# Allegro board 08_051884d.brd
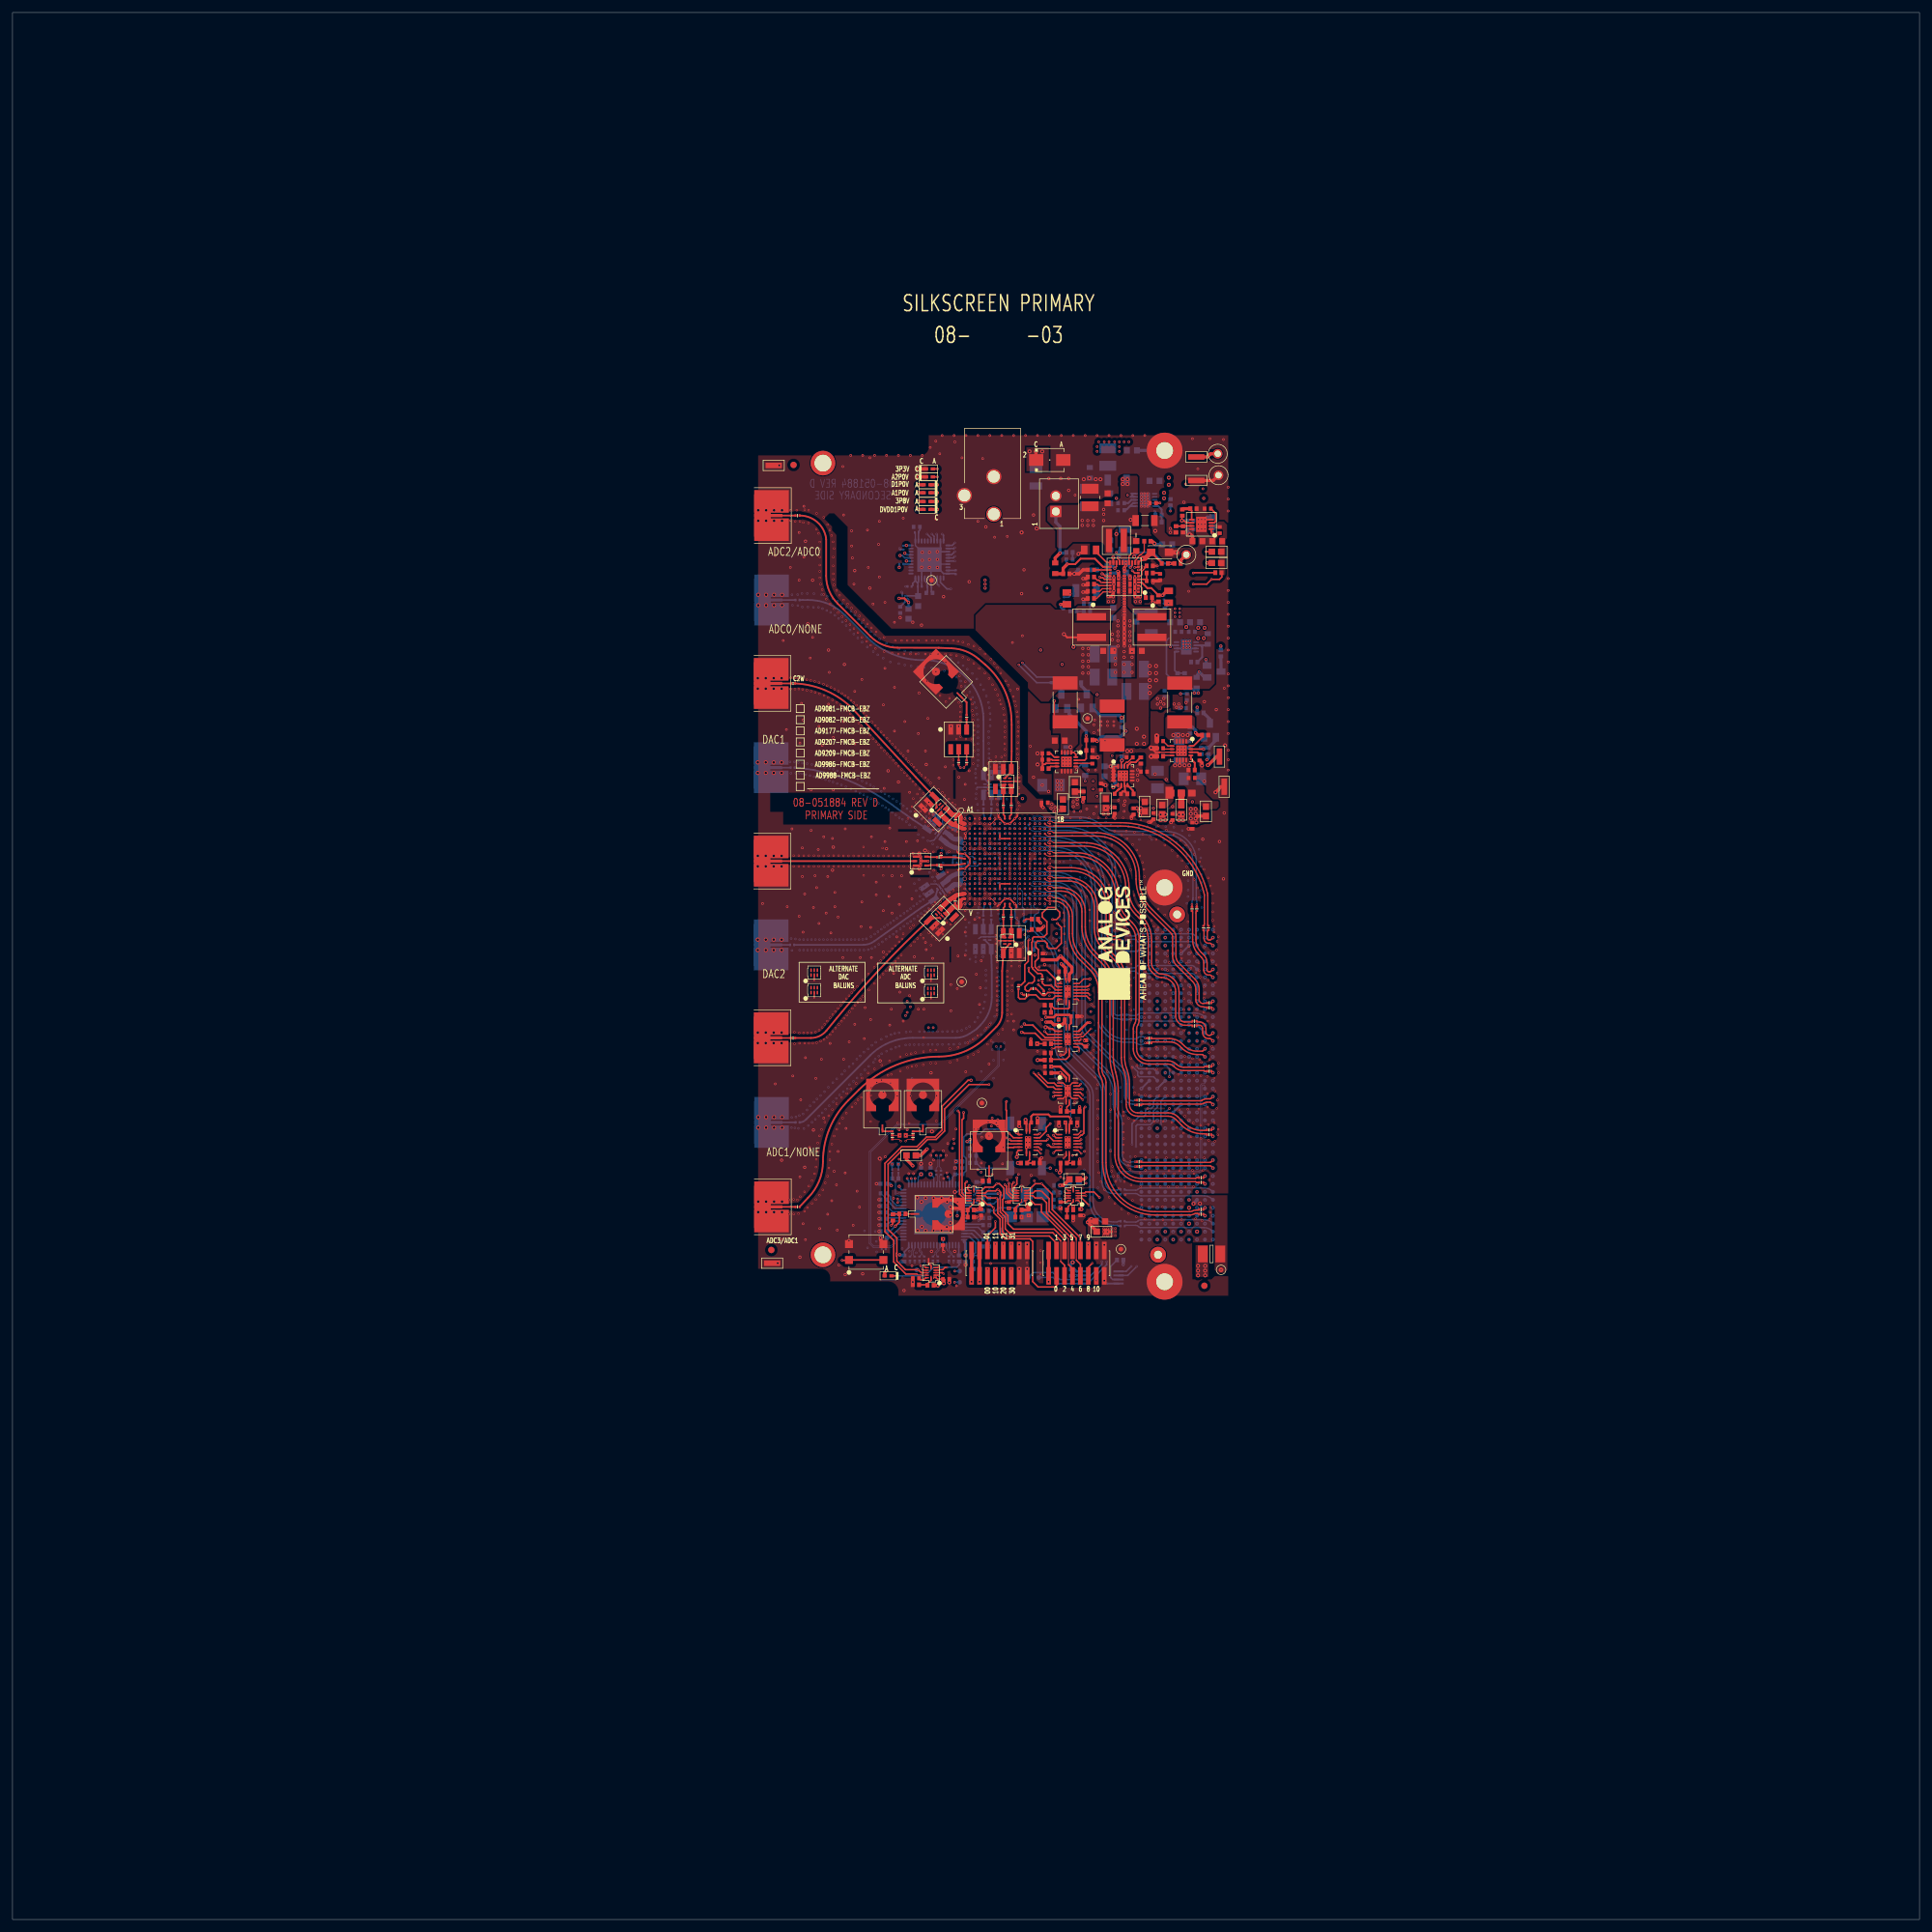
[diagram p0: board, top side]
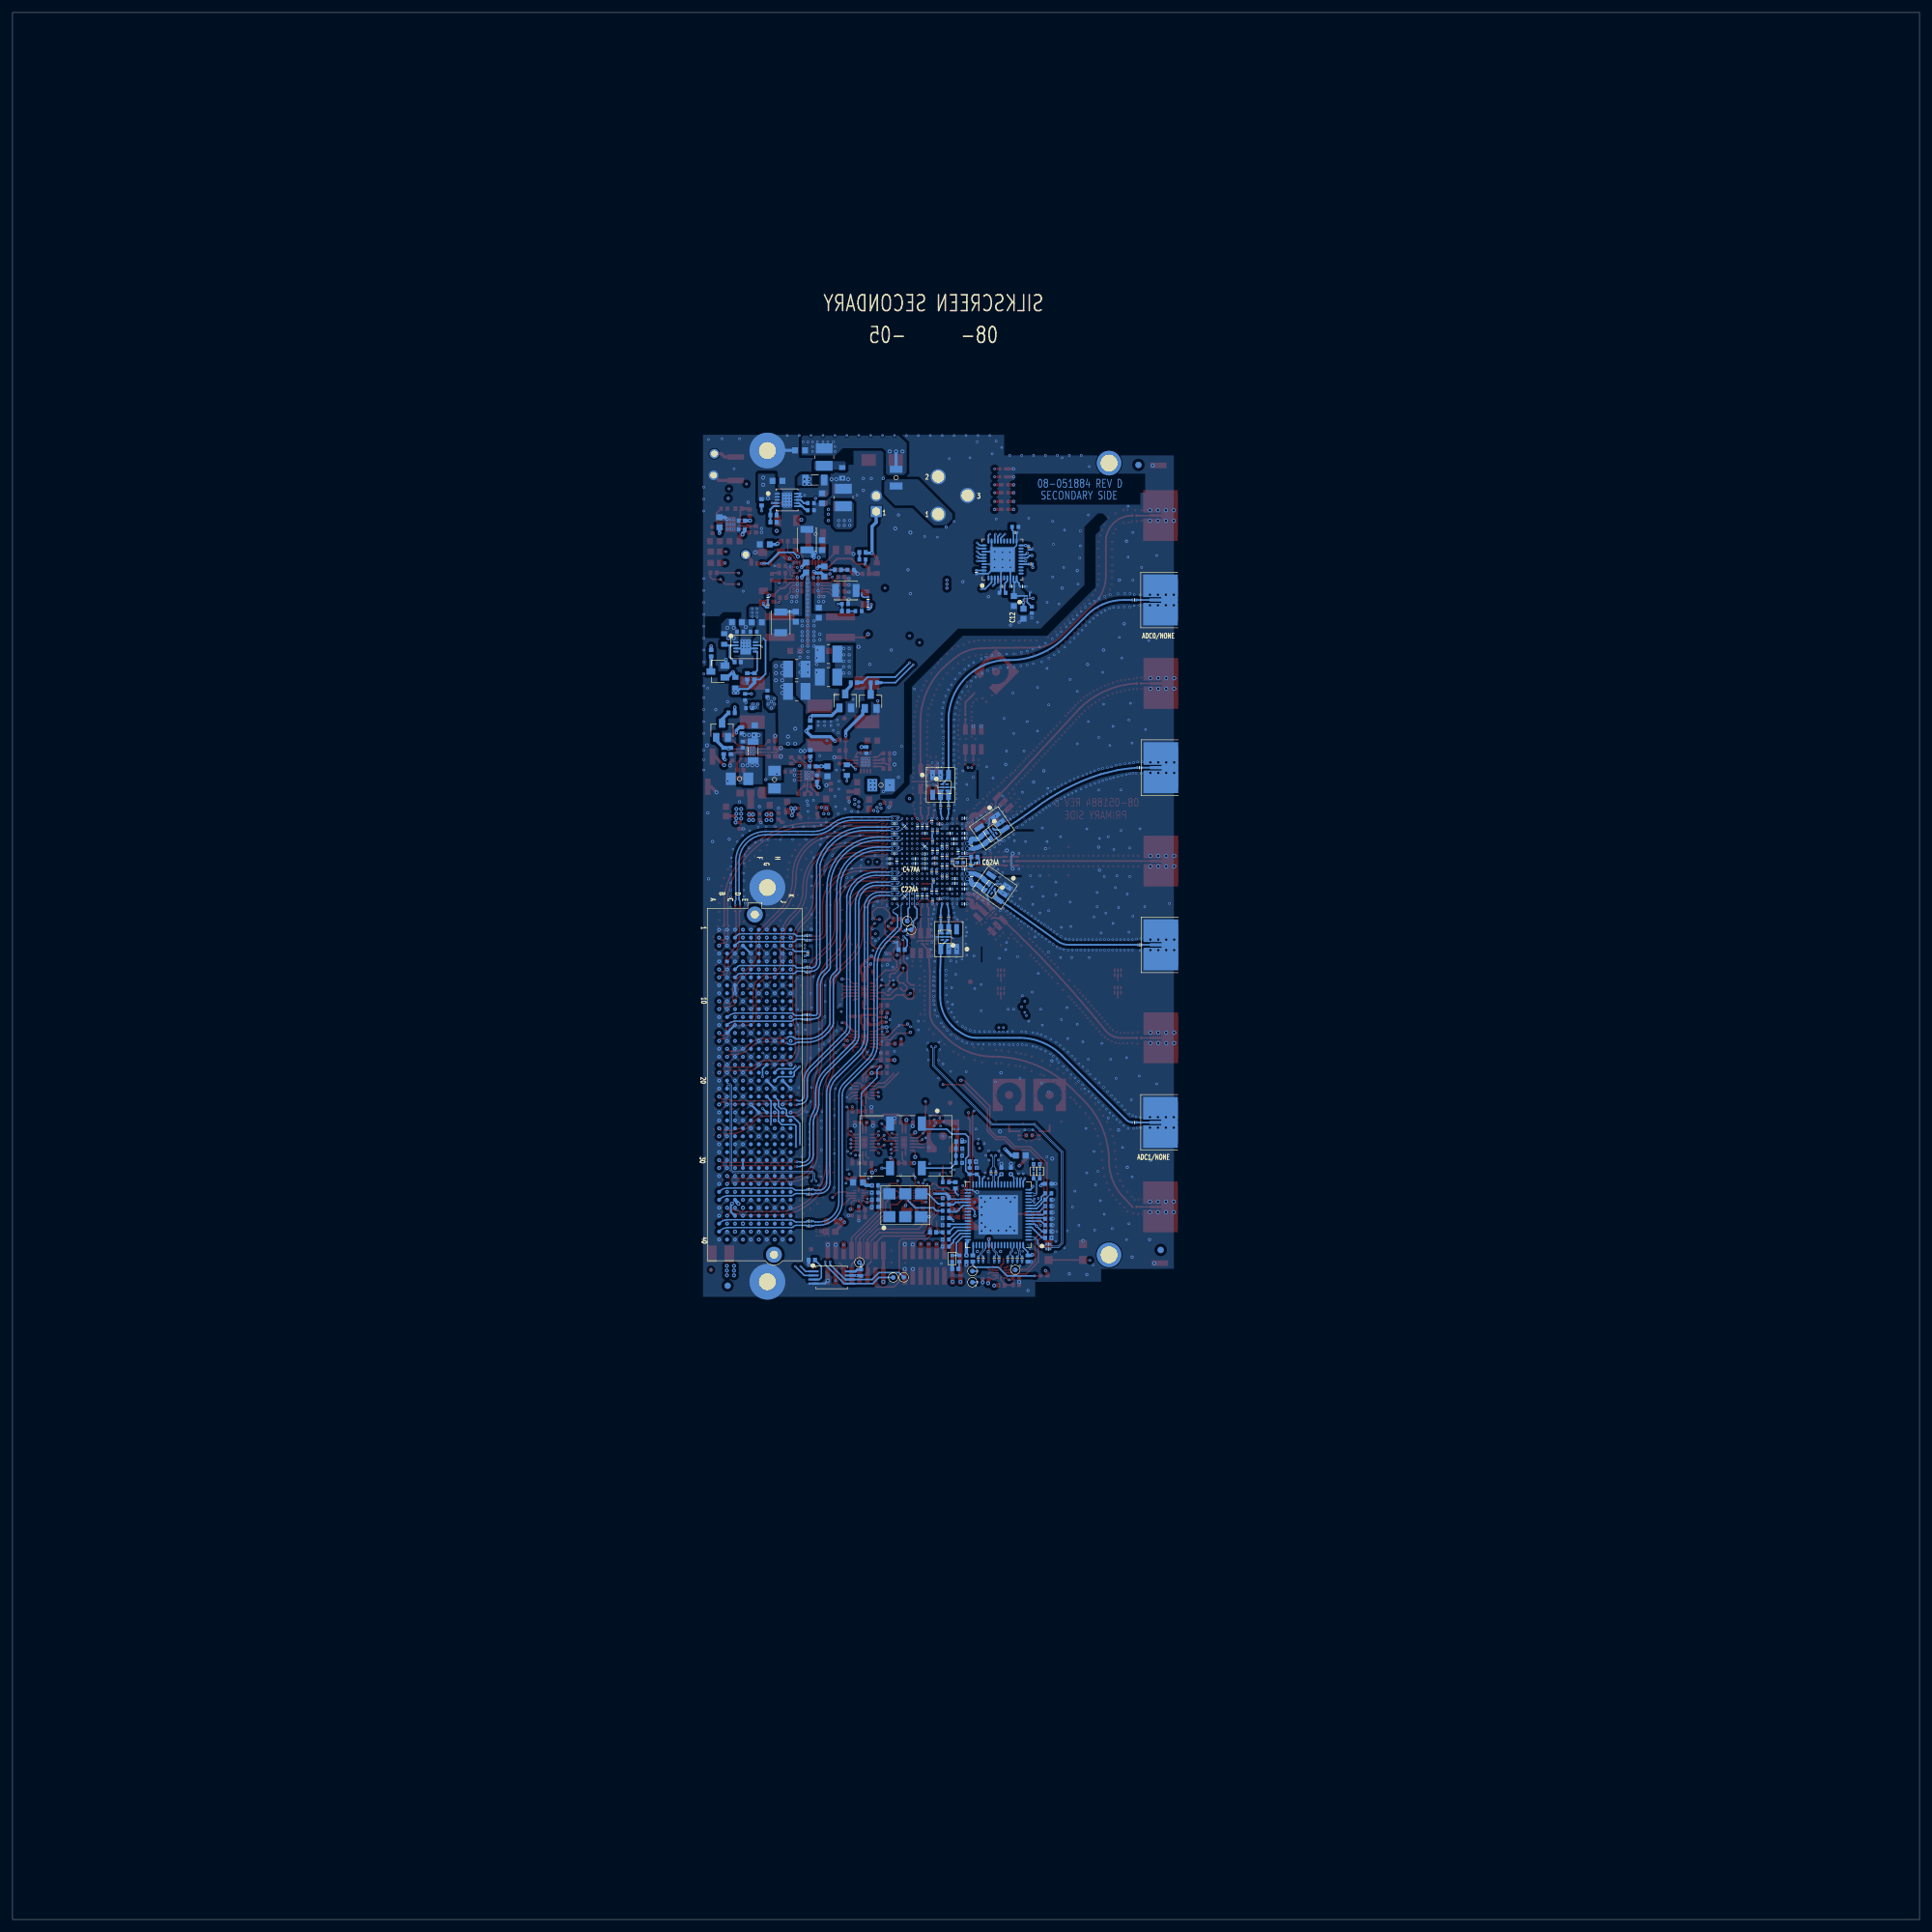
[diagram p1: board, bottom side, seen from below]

Outline 304.8 x 304.8 mm; copper layers: TOP, L2_GROUND, L3_SIGNAL, L4_GROUND, L5_POWER_ANALOG, L6_GROUND, L7_POWER_DIGITAL, L8_GROUND, L9_POWER_DVDD1, L10_SIGNAL, L11_GROUND, BOTTOM. Coordinates in mm from the lower left corner of the outline.
Outline path: 0,304.8 0,0 304.8,0 304.8,304.8 0,304.8

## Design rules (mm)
constraint set DEFAULT: min track width 0.241
net group CLK: nets HMC_CLK_N HMC_CLK_P
net group CLKOUT_0_N: nets CLKOUT_0_N UNNAMED_6_ADHMC7044_I49_CLKOUT0N
net group CLKOUT_0_P: nets CLKOUT_0_P UNNAMED_6_ADHMC7044_I49_CLKOUT0
net group CLKOUT_6_N: nets CLKOUT_6_N UNNAMED_6_ADHMC7044_I49_CLKOUT6N
net group CLKOUT_6_P: nets CLKOUT_6_P UNNAMED_6_ADHMC7044_I49_CLKOUT6_1
net group CLKOUT_8_N: nets CLKOUT_8_N UNNAMED_6_ADHMC7044_I49_CLKOUT8N
net group CLKOUT_8_P: nets CLKOUT_8_P UNNAMED_6_ADHMC7044_I49_CLKOUT8_1
net group CLKOUT_10_N: nets CLKOUT_10_N UNNAMED_6_ADHMC7044_I49_CLKOUT10N
net group CLKOUT_10_P: nets CLKOUT_10_P UNNAMED_6_ADHMC7044_I49_CLKOUT10
net group DAC0: nets DAC_N0 DAC_P0
net group DAC1: nets DAC_N1 DAC_P1
net group DAC2: nets DAC_N2 DAC_P2
net group DAC3: nets DAC_N3 DAC_P3
net group DP1: nets SYNCOUT_N0 SYNCOUT_P0
net group DP2: nets SYNCOUT_N1 SYNCOUT_P1
net group DP3: nets ADCDRV_N ADCDRV_P
net group DP4: nets UNNAMED_6_CAP_I146_N1 UNNAMED_6_CAP_I152_N1
net group FPGA_REFCLK_IN_N: nets FPGA_REFCLK_IN_N UNNAMED_6_ADHMC7044_I49_CLKOUT12N
net group FPGA_REFCLK_IN_P: nets FPGA_REFCLK_IN_P UNNAMED_6_ADHMC7044_I49_CLKOUT12
net group FPGA_SERDIN_N0: nets FPGA_SERDIN_N0 SERDOUT_N0
net group FPGA_SERDIN_N1: nets FPGA_SERDIN_N1 SERDOUT_N1
net group FPGA_SERDIN_N2: nets FPGA_SERDIN_N2 SERDOUT_N2
net group FPGA_SERDIN_N3: nets FPGA_SERDIN_N3 SERDOUT_N3
net group FPGA_SERDIN_N4: nets FPGA_SERDIN_N4 SERDOUT_N4
net group FPGA_SERDIN_N5: nets FPGA_SERDIN_N5 SERDOUT_N5
net group FPGA_SERDIN_N6: nets FPGA_SERDIN_N6 SERDOUT_N6
net group FPGA_SERDIN_N7: nets FPGA_SERDIN_N7 SERDOUT_N7
net group FPGA_SERDIN_P0: nets FPGA_SERDIN_P0 SERDOUT_P0
net group FPGA_SERDIN_P1: nets FPGA_SERDIN_P1 SERDOUT_P1
net group FPGA_SERDIN_P2: nets FPGA_SERDIN_P2 SERDOUT_P2
net group FPGA_SERDIN_P3: nets FPGA_SERDIN_P3 SERDOUT_P3
net group FPGA_SERDIN_P4: nets FPGA_SERDIN_P4 SERDOUT_P4
net group FPGA_SERDIN_P5: nets FPGA_SERDIN_P5 SERDOUT_P5
net group FPGA_SERDIN_P6: nets FPGA_SERDIN_P6 SERDOUT_P6
net group FPGA_SERDIN_P7: nets FPGA_SERDIN_P7 SERDOUT_P7
net group FPGA_SERDOUT_N0: nets FPGA_SERDOUT_N0 SERDIN_N0
net group FPGA_SERDOUT_N1: nets FPGA_SERDOUT_N1 SERDIN_N1
net group FPGA_SERDOUT_N2: nets FPGA_SERDOUT_N2 SERDIN_N2
net group FPGA_SERDOUT_N3: nets FPGA_SERDOUT_N3 SERDIN_N3
net group FPGA_SERDOUT_N4: nets FPGA_SERDOUT_N4 SERDIN_N4
net group FPGA_SERDOUT_N5: nets FPGA_SERDOUT_N5 SERDIN_N5
net group FPGA_SERDOUT_N6: nets FPGA_SERDOUT_N6 SERDIN_N6
net group FPGA_SERDOUT_N7: nets FPGA_SERDOUT_N7 SERDIN_N7
net group FPGA_SERDOUT_P0: nets FPGA_SERDOUT_P0 SERDIN_P0
net group FPGA_SERDOUT_P1: nets FPGA_SERDOUT_P1 SERDIN_P1
net group FPGA_SERDOUT_P2: nets FPGA_SERDOUT_P2 SERDIN_P2
net group FPGA_SERDOUT_P3: nets FPGA_SERDOUT_P3 SERDIN_P3
net group FPGA_SERDOUT_P4: nets FPGA_SERDOUT_P4 SERDIN_P4
net group FPGA_SERDOUT_P5: nets FPGA_SERDOUT_P5 SERDIN_P5
net group FPGA_SERDOUT_P6: nets FPGA_SERDOUT_P6 SERDIN_P6
net group FPGA_SERDOUT_P7: nets FPGA_SERDOUT_P7 SERDIN_P7
net group SYNCIN0: nets SYNCIN_N0 SYNCIN_P0
net group SYNCIN1: nets SYNCIN_N1 SYNCIN_P1
net group SYSREF: nets HMC_SYSREF_N HMC_SYSREF_P
net group SYSREF2_N: nets SYSREF2_N UNNAMED_6_ADHMC7044_I49_SCLKOUT13N
net group SYSREF2_P: nets SYSREF2_P UNNAMED_6_ADHMC7044_I49_SCLKOUT13
net group SYSREF3: nets SYSREF_N SYSREF_P

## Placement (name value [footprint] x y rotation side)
3P3V  RCU-0C  [CNTERCU]  192.91 185.88 90 top
12P0V  RCU-0C  [CNTERCU]  189.2 233.76 0 top
ADC0  142-0761-841  [CNSMAL554W247H118]  118.55 210.9 180 bottom
ADC1  142-0761-841  [CNSMAL554W247H118]  118.55 127.4 180 bottom
ADC2  142-0761-841  [CNSMAL554W247H118]  118.55 224.4 180 top
ADC3  142-0761-841  [CNSMAL554W247H118]  118.55 113.9 180 top
ADC_CLK  85305-0232  [CNSMASQ197H161]  149.22 197.82 45 top
AGC  FTSH-108-01-F-DV-K  [CNHDR2X8H251]  157.73 104.9 0 top
C1  1uF  [C0402]  146.56 212.04 0 bottom
C1A  10uF  [C1210-2]  175.06 233.75 270 bottom
C1AA  0.1uF  [C0201]  152.65 176.02 180 bottom
C1B  4.7uF  [C0402]  139.25 110.98 180 bottom
C1C  0.1uF  [C0201]  143.93 125.02 90 top
C1D  1.5pF  [C0402]  141.09 118.44 180 bottom
C1FF  0.1uF  [C0402]  164.68 153.89 270 top
C1G  0.1uF  [C0201]  177.75 157.28 180 bottom
C1H  0.1uF  [C0201]  177.75 156.51 180 bottom
C1I  0.1uF  [C0201]  189.28 161.52 90 top
C1J  0.1uF  [C0201]  188.52 161.52 90 top
C1K  0.1uF  [C0402]  169.16 103.38 270 bottom
C1LL  0.1uF  [C0603]  175.93 208.86 270 bottom
C1R  0.1uF  [C0201]  151.23 184.94 90 top
C1S  0.1uF  [C0201]  155.19 177.9 90 bottom
C1T  0.1uF  [C0201]  156.44 160.14 270 bottom
C1U  0.1uF  [C0201]  159.64 178.05 90 top
C1V  0.1uF  [C0201]  158.37 160.25 270 top
C1X  10uF  [C0603]  174.55 183.52 270 bottom
C2  1uF  [C0402]  144.52 222.58 180 bottom
C2A  0.1uF  [C0603]  178.92 234.81 0 bottom
C2AA  0.1uF  [C0201]  154.94 173.61 0 bottom
C2B  4.7uF  [C0402]  139.25 112 180 bottom
C2C  0.1uF  [C0201]  143.93 125.65 90 top
C2D  1.5pF  [C0402]  141.09 120.73 180 bottom
C2FF  0.1uF  [C0402]  169.67 144.35 180 top
C2G  0.1uF  [C0201]  191.26 126.21 180 top
C2H  0.1uF  [C0201]  191.26 125.45 180 top
C2I  0.1uF  [C0201]  177.75 152.2 180 bottom
C2J  0.1uF  [C0201]  177.75 151.43 180 bottom
C2LL  10pF  [C0402]  171.74 210.26 180 bottom
C2M  10uF  [C0603]  186.18 190.07 90 bottom
C2NN  10uF  [C0603]  167.38 188.42 180 top
C2P  10uF  [C0603]  189.39 220.29 0 top
C2Q  10uF  [C0603]  185.83 207.34 0 bottom
C2R  0.1uF  [C0201]  152.5 184.94 90 top
C2S  0.1uF  [C0201]  156.46 177.9 90 bottom
C2T  0.1uF  [C0201]  155.17 160.14 270 bottom
C2U  0.1uF  [C0201]  158.37 178.05 90 top
C2V  0.1uF  [C0201]  159.64 160.25 270 top
C2W  0.1uF  [C0201]  124.76 197.56 180 top
C2X  0.1uF  [C0201]  124.69 184.1 180 bottom
C2XA  1uF  [C0402]  176.91 184.3 0 bottom
C2Y  0.1uF  [C0201]  124.61 155.78 180 bottom
C2Z  0.1uF  [C0201]  124.76 140.9 180 top
C3  0.1uF  [C0201]  155.45 168.35 270 bottom
C3B  1uF  [C0402]  166.94 113.9 0 bottom
C3C  0.1uF  [C0201]  140.63 125.02 90 top
C3D  0.1uF  [C0201]  148.4 170.11 270 top
C3FF  0.1uF  [C0402]  165.5 136.32 0 top
C3G  0.1uF  [C0201]  189.99 118.57 180 top
C3H  0.1uF  [C0201]  189.99 117.81 180 top
C3I  0.1uF  [C0201]  177.77 144.6 180 bottom
C3J  0.1uF  [C0201]  177.77 143.84 180 bottom
C3LL  0.1uF  [C0603]  179.61 208.23 270 bottom
C3M  1uF  [C0402]  188.08 187.78 270 bottom
C3NN  1uF  [C0402]  168.3 186.89 270 bottom
C3P  1uF  [C0402]  188.25 222.2 0 bottom
C3R  0.1uF  [C0201]  152.5 192.18 90 top
C3S  0.1uF  [C0201]  125.48 210.9 180 bottom
C3T  0.1uF  [C0201]  125.47 127.41 180 bottom
C3U  0.1uF  [C0201]  125.48 224.4 180 top
C3V  0.1uF  [C0201]  125.48 113.9 180 top
C4  0.1uF  [C0201]  150.75 215.34 270 bottom
C4AA  0.1uF  [C0201]  152.65 172.85 180 bottom
C4B  1uF  [C0402]  153.52 122.07 180 bottom
C4C  0.1uF  [C0201]  140.63 125.65 90 top
C4D  0.1uF  [C0201]  148.08 169.8 180 top
C4FF  0.1uF  [C0402]  167.77 151.51 180 top
C4G  0.1uF  [C0201]  189.99 113.49 180 top
C4H  0.1uF  [C0201]  189.99 112.73 180 top
C4I  0.1uF  [C0201]  181.71 140.87 180 top
C4J  0.1uF  [C0201]  181.71 140.11 180 top
C4LL  100uF  [C1210-2]  174.37 202.26 0 bottom
C4M  1uF  [C0402]  183.41 187.2 180 top
C4NN  1uF  [C0402]  165.1 185.37 180 top
C4P  1uF  [C0402]  191.04 225.5 180 top
C4Q  1uF  [C0402]  186.34 205.82 0 bottom
C4X  1uF  [C0402]  176.65 179.91 0 top
C5  0.1uF  [C0201]  146.56 213.06 0 bottom
C5AA  0.1uF  [C0201]  154.31 172.72 0 bottom
C5B  4.7uF  [C0402]  139.25 113.02 180 bottom
C5D  0.1uF  [C0201]  148.39 168.21 90 top
C5FF  0.1uF  [C0402]  167.69 143.84 180 top
C5G  0.1uF  [C0201]  180.06 130.96 180 top
C5H  0.1uF  [C0201]  180.06 130.2 180 top
C5I  0.1uF  [C0201]  191.29 136.35 180 top
C5J  0.1uF  [C0201]  191.29 135.59 180 top
C5LL  0.1uF  [C0603]  175.13 202.77 0 top
C5M  1uF  [C0402]  183.41 188.34 180 top
C5NN  1uF  [C0402]  165.1 186.39 180 top
C5OO  1uF  [C0402]  177.2 226.39 180 bottom
C5P  10uF  [C0603]  191.8 223.34 90 bottom
C5Q  10uF  [C0603]  189.01 207.34 180 bottom
C5X  1uF  [C0402]  176.22 182.37 90 bottom
C6  0.1uF  [C0201]  144.52 221.69 180 bottom
C6AA  0.1uF  [C0201]  155.45 169.88 90 bottom
C6B  0.1uF  [C0402]  166.94 115.05 0 bottom
C6D  0.1uF  [C0201]  148.08 168.53 180 top
C6FF  0.1uF  [C0402]  165.53 135.31 180 top
C6G  0.1uF  [C0201]  177.44 111.61 180 bottom
C6H  0.1uF  [C0201]  177.44 110.85 180 bottom
C6I  0.1uF  [C0201]  188.92 143.59 180 top
C6J  0.1uF  [C0201]  188.92 142.82 180 top
C6LL  10pF  [C0402]  172.37 215.72 180 top
C6M  0.01uF  [C0402]  189.74 185.75 270 top
C6NN  10uF  [C0402]  171.19 179.78 270 top
C6OO  10uF  [C0603]  143.63 122.12 180 bottom
C6P  10uF  [C0402]  187.7 195.4 270 bottom
C6Q  1uF  [C0402]  188.5 205.82 180 bottom
C6X  0.01uF  [C0402]  178.56 185.75 180 top
C7  0.1uF  [C0201]  145.03 213.06 0 bottom
C7AA  0.1uF  [C0201]  152.65 170.43 180 bottom
C7B  0.1uF  [C0402]  153.52 123.22 180 bottom
C7G  0.1uF  [C0201]  177.44 116.69 180 bottom
C7H  0.1uF  [C0201]  177.44 115.93 180 bottom
C7I  0.1uF  [C0201]  191.29 146.51 180 top
C7J  0.1uF  [C0201]  191.29 145.75 180 top
C7LL  4.7uF  [C1206H71-2]  183.42 218.52 0 top
C7M  47uF  [C1206H71]  188.59 182.32 0 bottom
C7NN  10uF  [C0402]  176.15 177.24 270 top
C7OO  10uF  [C0603]  175.42 227.15 270 bottom
C7P  1uF  [C0402]  188.25 223.6 0 bottom
C7X  47uF  [C1206H71]  183 182.2 90 bottom
C8  0.1uF  [C0201]  143.38 213.06 180 bottom
C8AA  0.1uF  [C0201]  154.31 171.96 0 bottom
C8B  1uF  [C0402]  139.25 115.05 180 bottom
C8FF  0.1uF  [C0402]  163.32 127.38 180 top
C8G  0.1uF  [C0201]  180.06 121.11 180 top
C8H  0.1uF  [C0201]  180.06 120.35 180 top
C8I  0.1uF  [C0201]  191.13 158.5 90 top
C8J  0.1uF  [C0201]  190.37 158.5 90 top
C8LL  4.7uF  [C0603]  184.56 219.79 0 bottom
C8M  1uF  [C0402]  188.47 182.45 0 top
C8NN  0.01uF  [C0402]  172.59 185.24 90 top
C8OO  10uF  [C0603]  169.67 117.81 0 bottom
C8P  10uF  [C0603]  192.54 220.29 180 top
C8X  1uF  [C0402]  180.85 183.47 0 top
C9  0.1uF  [C0201]  142.36 219.28 270 bottom
C9AA  0.1uF  [C0201]  156.21 169.93 90 bottom
C9B  100pF  [C0402]  166.94 116.19 0 bottom
C9FF  0.1uF  [C0402]  169.67 127.38 180 top
C9LL  1000pF  [C0402]  183.42 214.58 270 top
C9M  10uF  [C0402]  188.59 174.83 270 top
C9NN  47uF  [C1206H71]  165.99 181.31 180 bottom
C9OO  1uF  [C0402]  177.2 225.25 180 bottom
C9P  1uF  [C0402]  192.94 222.07 270 top
C9X  10uF  [C0402]  179.19 177.12 270 top
C10  0.01uF  [C0201]  168.05 209.75 270 bottom
C10AA  0.1uF  [C0201]  152.63 167.87 180 bottom
C10B  100pF  [C0402]  153.52 120.93 180 bottom
C10FF  0.1uF  [C0402]  161.42 127.38 180 top
C10LL  10pF  [C0402]  181.77 213.94 0 top
C10NN  1uF  [C0402]  173.99 181.05 90 top
C10X  10uF  [C0402]  185.42 176.23 270 top
C11  0.01uF  [C0201]  184.05 210.01 270 bottom
C11AA  0.1uF  [C0201]  154.18 166.37 0 bottom
C11B  0.1uF  [C0402]  155.63 114.29 180 bottom
C11FF  0.1uF  [C0402]  167.77 127.38 180 top
C11LL  0.1uF  [C0603]  177.96 216.1 270 bottom
C12  2.2uF  [C0603]  144.75 210.73 270 bottom
C12AA  0.1uF  [C0201]  156.21 168.4 270 bottom
C12B  0.1uF  [C0402]  155.63 113.27 180 bottom
C12FF  0.1uF  [C0402]  151.64 114.17 90 top
C12LL  0.1uF  [C0603]  175.04 215.47 90 bottom
C12N  10uF  [C0402]  164.97 178.51 180 top
C13  2.2uF  [C0603]  143.22 208.7 270 bottom
C13AA  0.1uF  [C0201]  152.65 165.48 180 bottom
C13B  0.1uF  [C0402]  155.63 117.84 180 bottom
C13FF  0.1uF  [C0402]  159.26 114.17 90 top
C13LL  0.01uF  [C0402]  168.94 217.37 0 bottom
C14  1000pF  [C0402]  141.88 209.31 270 bottom
C14AA  0.1uF  [C0201]  154.18 165.61 0 bottom
C14FF  0.1uF  [C0402]  167.51 114.17 90 top
C14LL  0.1uF  [C0603]  179.61 219.53 90 top
C14OO  1uF  [C0402]  182.28 226.39 180 top
C15  10uF  [C0402]  184.15 195.91 90 bottom
C15AA  0.1uF  [C0201]  155.45 171.58 270 bottom
C15B  0.1uF  [C0402]  155.63 109.84 180 bottom
C15FF  0.1uF  [C0402]  154.81 113.03 270 top
C16  10uF  [C0402]  187.07 193.63 0 bottom
C16AA  0.1uF  [C0201]  152.65 162.31 180 bottom
C16B  0.1uF  [C0402]  155.63 108.7 180 bottom
C16FF  0.1uF  [C0402]  162.43 113.03 270 top
C17  0.1uF  [C0201]  157.73 162.76 270 bottom
C17AA  0.1uF  [C0201]  154.94 164.72 0 bottom
C17B  0.1uF  [C0402]  139.25 116.06 180 bottom
C17FF  0.1uF  [C0402]  170.69 113.03 270 top
C17OO  10uF  [C0603]  173.86 111.58 0 top
C18  0.1uF  [C0201]  157.86 175.59 90 bottom
C18AA  0.1uF  [C0201]  155.45 166.75 90 bottom
C18B  4.7uF  [C0402]  155.63 110.98 0 bottom
C18FF  0.1uF  [C0402]  144.4 102.49 0 top
C19  0.1uF  [C0201]  156.59 163.15 180 bottom
C19AA  0.1uF  [C0201]  158.62 174.75 90 bottom
C19B  4.7uF  [C0402]  155.63 107.55 0 bottom
C19FF  0.1uF  [C0402]  149.22 102.36 0 top
C20  0.1uF  [C0201]  156.59 175.08 180 bottom
C20AA  0.1uF  [C0201]  159 173.61 180 bottom
C20B  0.1uF  [C0402]  139.25 114.03 0 bottom
C21AA  0.1uF  [C0201]  158.62 163.58 270 bottom
C21B  0.1uF  [C0402]  139.25 117.59 0 bottom
C22AA  0.1uF  [C0201]  159 164.72 180 bottom
C22B  0.1uF  [C0402]  145.22 119.62 270 bottom
C22LL  100uF  [C1210-2]  171.99 227.28 90 bottom
C23AA  0.1uF  [C0201]  157.73 173.99 90 bottom
C23B  0.1uF  [C0402]  146.74 119.62 270 bottom
C23LL  100uF  [C1210-2]  179.45 199.85 180 bottom
C23X  10uF  [C0402]  182.37 176.35 270 top
C24AA  0.1uF  [C0201]  159.38 174.75 90 bottom
C24B  0.1uF  [C0402]  155.63 115.3 180 bottom
C24LL  100uF  [C1210-2]  172.24 227.28 90 top
C25AA  0.1uF  [C0201]  157.73 172.34 270 bottom
C25B  0.1uF  [C0402]  155.63 112.13 180 bottom
C25LL  0.1uF  [C0603]  175.42 219.66 90 bottom
C26B  0.1uF  [C0402]  142.55 105.65 270 bottom
C27AA  0.1uF  [C0201]  159.38 163.58 270 bottom
C27B  0.1uF  [C0402]  148.71 108.28 270 top
C27LL  100uF  [C1210-2]  179.45 196.29 180 bottom
C28B  0.1uF  [C0402]  152.33 105.65 270 bottom
C28LL  0.1uF  [C0603]  175.04 227.15 90 top
C29AA  0.1uF  [C0201]  156.97 173.99 90 bottom
C29B  0.1uF  [C0201]  139.25 107.17 180 bottom
C29LL  0.1uF  [C0603]  179.7 202.77 180 top
C30AA  0.1uF  [C0201]  156.97 170.81 270 bottom
C30B  0.1uF  [C0201]  139.25 107.94 180 bottom
C30LL  22uF  [C1210H106]  182.02 207.34 270 bottom
C31AA  0.1uF  [C0201]  157.1 164.34 270 bottom
C31B  0.1uF  [C0201]  147.63 119.37 90 bottom
C31LL  22uF  [C1210H106]  171.61 212.42 180 bottom
C32AA  0.1uF  [C0201]  157.73 170.81 270 bottom
C32B  0.1uF  [C0201]  148.39 119.37 90 bottom
C33AA  0.1uF  [C0201]  157.61 165.99 90 bottom
C33B  0.1uF  [C0201]  150.43 105.65 270 bottom
C34AA  0.1uF  [C0201]  160.15 174.75 270 bottom
C34B  0.1uF  [C0201]  149.66 105.65 270 bottom
C35AA  0.1uF  [C0201]  157.1 167.51 90 bottom
C35B  0.1uF  [C0201]  147.89 105.65 270 bottom
C36AA  0.1uF  [C0201]  157.86 164.34 270 bottom
C36B  0.1uF  [C0201]  147.12 105.65 270 bottom
C37AA  0.1uF  [C0201]  160.15 163.58 90 bottom
C37B  0.1uF  [C0201]  144.2 105.65 270 bottom
C38AA  0.1uF  [C0201]  157.86 167.51 90 bottom
C38B  0.1uF  [C0201]  143.44 105.65 270 bottom
C39AA  0.1uF  [C0201]  156.21 171.58 90 bottom
C39B  0.1uF  [C0201]  145.73 105.65 270 bottom
C40AA  0.1uF  [C0201]  156.21 166.75 270 bottom
C40B  0.1uF  [C0201]  144.96 105.65 270 bottom
C40LL  2200pF  [C0402]  170.85 215.72 180 bottom
C41AA  0.1uF  [C0201]  159 170.31 0 bottom
C41B  160pF  [C0402H22]  154.62 105.65 270 bottom
C41LL  22uF  [C1210H106]  177.83 220.55 90 bottom
C42AA  0.1uF  [C0201]  157.35 169.67 0 bottom
C42B  4700pF  [C0402]  153.47 105.65 270 bottom
C42LL  100uF  [C1210-2]  174.37 198.58 0 bottom
C43AA  0.1uF  [C0201]  159 169.55 0 bottom
C43B  4700pF  [C0402]  150.68 119.62 90 bottom
C43LL  1000pF  [C0402]  169.58 209.12 180 bottom
C44AA  0.1uF  [C0201]  157.35 168.78 0 bottom
C44B  1uF  [C0402]  151.82 119.62 90 bottom
C45AA  0.1uF  [C0201]  160.53 169.55 0 bottom
C46AA  0.1uF  [C0201]  159 168.78 0 bottom
C47AA  0.1uF  [C0201]  160.53 168.78 0 bottom
C48AA  0.1uF  [C0201]  152.65 173.61 180 bottom
C49AA  0.1uF  [C0201]  159 168.02 0 bottom
C50AA  0.1uF  [C0201]  152.65 164.72 180 bottom
C51AA  0.1uF  [C0201]  163.45 169.16 90 bottom
C52AA  0.1uF  [C0201]  163.83 175.16 180 bottom
C53AA  0.1uF  [C0201]  164.59 169.55 0 bottom
C54AA  0.1uF  [C0201]  163.83 173.56 180 bottom
C55AA  0.1uF  [C0201]  164.59 168.78 0 bottom
C56AA  0.1uF  [C0201]  163.83 171.96 180 bottom
C57AA  0.1uF  [C0201]  163.83 166.36 180 bottom
C58AA  0.1uF  [C0201]  163.83 170.36 180 bottom
C59AA  0.1uF  [C0201]  163.83 164.76 180 bottom
C60AA  0.1uF  [C0201]  163.83 163.14 180 bottom
C62AA  0.022uF  [C0201]  150.62 168.86 0 bottom
C63AA  0.033uF  [C0201]  154.63 169.09 90 bottom
C65AA  2200pF  [C0201]  151.64 168.61 270 bottom
C69AA  2.2uF  [C0402H22]  153.29 168.94 180 bottom
C70AA  0.1uF  [C0201]  159 171.53 225 bottom
C71AA  0.1uF  [C0201]  162.18 163.53 315 bottom
C72AA  0.1uF  [C0201]  162.18 174.7 45 bottom
C100  10uF  [C0603]  182.53 229.95 180 bottom
D1A  SMAJ12A  [DIOSMJ5_0]  165.78 233.28 0 top
DAC0  142-0761-841  [CNSMAL554W247H118]  118.49 197.56 180 top
DAC1  142-0761-841  [CNSMAL554W247H118]  118.49 184.1 180 bottom
DAC2  142-0761-841  [CNSMAL554W247H118]  118.49 155.78 180 bottom
DAC3  142-0761-841  [CNSMAL554W247H118]  118.49 140.92 180 top
DS1M  APHHS1005LSYCK/J3-PF  [LED0402_A]  146.17 225.38 180 top
DS1NN  APHHS1005LSYCK/J3-PF  [LED0402_A]  146.17 228.04 180 top
DS1P  APHHS1005LSYCK/J3-PF  [LED0402_A]  146.56 230.58 0 top
DS1Q  APHHS1005LSYCK/J3-PF  [LED0402_A]  146.17 226.65 180 top
DS1X  APHHS1005LSYCK/J3-PF  [LED0402_A]  146.17 229.31 180 top
DS100  APHHS1005LSYCK/J3-PF  [LED0402_A]  146.56 231.85 0 top
E1  22OHM AT 100 MEGHZ  [L0603H28]  192.45 216.82 180 top
E1B  120OHM  [L0402]  166.94 117.33 180 bottom
E1M  22OHM AT 100 MEGHZ  [L0603H28]  190.75 177.12 270 top
E1NN  22OHM AT 100 MEGHZ  [L0603H28]  169.8 181.03 270 top
E1OO  22OHM AT 100 MEGHZ  [L0603H28]  143.63 122.12 0 top
E1XX  22OHM AT 100 MEGHZ  [L0603H28]  180.97 177.88 270 top
E2  22OHM AT 100 MEGHZ  [L0603H28]  192.45 218.62 180 top
E2B  120OHM  [L0402]  153.52 124.36 0 bottom
E2NN  22OHM AT 100 MEGHZ  [L0603H28]  174.75 178.39 270 top
E2OO  22OHM AT 100 MEGHZ  [L0603H28]  174.04 109.93 180 top
E2XX  22OHM AT 100 MEGHZ  [L0603H28]  186.81 177.37 270 top
E3OO  22OHM AT 100 MEGHZ  [L0603H28]  169.67 118.31 180 top
E4NN  22OHM AT 100 MEGHZ  [L0603H28]  167.89 178.26 270 top
E4X  22OHM AT 100 MEGHZ  [L0603H28]  183.77 177.37 270 top
EXT_CLK  142-0761-841  [CNSMAL554W247H118]  118.49 169.17 180 top
EXT_HMCREF  85305-0232  [CNSMASQ197H161]  156.08 122.94 0 top
EXT_SYNC  85305-0232  [CNSMASQ197H161]  147.32 112.78 270 top
EXT_SYS_N  85305-0232  [CNSMASQ197H161]  139.04 129.49 0 top
EXT_SYS_P  85305-0232  [CNSMASQ197H161]  145.52 129.49 0 top
F1A  3A  [F1206]  163.57 230.46 90 bottom
GND0  RCU-0C  [CNTERCU]  189.2 230 0 top
GND1  RCU-0C  [CNTERCU]  193.67 181.05 270 top
GND2  RCU-0C  [CNTERCU]  121.67 232.41 0 top
GND3  RCU-0C  [CNTERCU]  121.41 104.9 0 top
GPIO  FTSH-108-01-F-DV-K  [CNHDR2X8H251]  170.05 104.9 0 top
HMC_STATUS  APHHS1005SURCK  [LED0402_A]  139.95 102.87 180 top
JP1  3PINJUMPER0603  [JUMPER0603_3P]  186.81 180.04 180 top
L1D  3.6nH  [L0201]  141.6 119.58 90 bottom
L1LL  800nH  [LSML208W216H122_A]  182.12 206.58 270 top
L2D  3.6nH  [L0201]  140.59 119.58 90 bottom
L2LL  800nH  [LSML208W216H122_A]  172.46 206.58 270 top
L3LL  4.7uH  [LSMSQ157H122]  176.43 220.42 180 top
NOREF  -  []  118.55 103.35 90 top
NOREF#2  -  []  118.55 103.35 90 top
NOREF#3  -  [unnamed#2]  129.54 106.24 0 top
NOREF#4  -  [unnamed#2]  129.54 232.78 0 top
NOREF#5  -  []  118.55 103.35 0 top
NOREF#6  -  []  84.33 219.91 270 top
NOREF#7  -  [unnamed#2]  124.84 232.49 0 top
NOREF#8  -  []  258.57 278.46 0 top
NOREF#9  -  []  406.65 57.74 0 top
NOREF#10  -  []  118.55 234.65 0 top
NOREF#11  -  []  118.55 103.35 0 top
NOREF#12  -  []  177.37 156.57 90 top
NOREF#13  -  []  145.65 237.95 0 top
NOREF#14  -  []  -222.25 -146.05 0 top
NOREF#15  -  []  -222.25 -146.05 0 top
NOREF#16  -  [unnamed#2]  121.28 107.01 0 top
NOREF#17  -  []  140.85 98.95 90 top
NOREF#18  -  []  -222.25 -146.05 0 top
NOREF#19  -  [unnamed#2]  190.5 101.3 0 top
NOREF#20  -  []  157.61 252.1 0 top
NOREF#21  -  []  -70.61 283.16 0 top
NOREF#22  -  []  130.05 101.25 90 top
NOREF#23  -  []  177.8 304.8 0 top
NOREF#24  -  []  195.04 98.95 90 top
NOREF#25  -  []  118.55 103.35 0 top
NOREF#26  -  [unnamed#2]  124.84 232.49 180 bottom
NOREF#27  -  [unnamed#2]  121.28 107.01 180 bottom
NOREF#28  -  [unnamed#2]  190.5 101.3 180 bottom
P1  B2B-XH-A(LF)(SN)  [CNHDR1X2H276]  166.76 225.04 90 top
P1AA  PJ-102AH  [CNCUI-PJ-102A]  156.84 224.61 90 top
P1K  ASP-134488-01  [CNSAMTECASP-134488-01]  186.15 133.44 270 bottom
Q1M  NDS331N  [SOT23]  191.39 190.07 180 bottom
Q1NN  NDS331N  [SOT23]  167.64 194.69 180 bottom
Q1Q  NDS331N  [SOT23]  192.06 199.47 90 bottom
Q1X  NDS331N  [SOT23]  171.7 194.77 180 bottom
R1  0.05  [R2512H35]  168.25 194.54 270 top
R1A  10  [R0603]  172.19 231.22 270 bottom
R1B  56.2  [R0402]  157.66 109.84 180 bottom
R1C  100  [R0402]  142.28 125.34 180 top
R1E  0  [R0402]  140.71 112.22 90 top
R1FF  10K  [R0402]  171.55 140.03 270 top
R1K  10K  [R0402]  177.04 105.41 0 bottom
R1LL  10K  [R0402]  171.74 209.12 180 bottom
R1M  0.05  [R2512H35]  186.56 194.51 270 top
R1Q  2K  [R0402]  193.13 202.39 270 bottom
R1W  100  [R0201]  150.75 175.74 270 top
R1X  100  [R0201]  151.51 171.65 270 bottom
R1XA  0.05  [R2512H35]  175.77 190.83 270 top
R1Y  100  [R0201]  151.51 166.7 270 bottom
R1Z  100  [R0201]  150.67 162.76 270 top
R2  0  [R1210]  191.64 106.38 180 top
R2AA  4.99K  [R0201]  153.64 170.69 90 bottom
R2B  1K  [R0402]  151.31 105.65 270 bottom
R2E  0  [R0402]  142.24 112.78 0 top
R2FF  10K  [R0402]  165.48 144.98 180 top
R2K  0  [R0201]  177.67 154.43 270 bottom
R2LL  0  [R0402]  172.37 211.15 180 top
R2M  100K  [R0402]  188.21 190.07 90 bottom
R2P  100K  [R0402]  187.1 222.2 90 top
R3  33  [R0201]  142.05 216.65 180 bottom
R3AA  226  [R0402]  151.08 169.82 180 bottom
R3B  10K  [R0402]  139.25 109.97 180 bottom
R3FF  10K  [R0402]  165.48 146.13 180 top
R3M  100K  [R0402]  190.62 189.31 0 top
R3P  71.5K  [R0402]  185.96 222.2 270 top
R4  10K  [R0402]  163.41 158.24 180 top
R4B  10K  [R0402]  139.25 108.95 180 bottom
R4FF  10K  [R0402]  165.48 137.36 180 top
R4LL  10K  [R0402]  172.37 214.58 180 top
R4M  10K  [R0402]  183.41 185.93 180 top
R4NN  10K  [R0402]  165.1 183.95 180 top
R4Q  100K  [R0603]  189.26 197.69 90 bottom
R4X  10K  [R0402]  178.69 179.91 180 top
R5  10K  [R0402]  163.41 159.89 180 top
R5B  430  [R0402]  154.11 104 0 bottom
R5FF  10K  [R0402]  165.48 138.51 180 top
R5P  10K  [R0402]  186.98 224.87 90 top
R5X  10  [R0402]  180.34 185.24 90 top
R6  33  [R0201]  163.17 148.79 180 top
R6B  11K  [R0402]  151.31 121.14 180 bottom
R6FF  10K  [R0402]  170.05 129.16 0 top
R6M  100K  [R0402]  191.13 186.77 90 bottom
R6NN  100K  [R0402]  172.12 188.52 180 top
R6P  15K  [R0402]  188.75 225.5 0 top
R6Q  100K  [R0402]  186.21 198.7 90 bottom
R6X  100K  [R0402]  177.29 191.09 90 bottom
R7  33  [R0201]  160.78 149.05 90 top
R7FF  10K  [R0402]  168.02 129.16 180 top
R7LL  1K  [R0402]  184.18 216.74 0 top
R7M  2K  [R0402]  189.86 192.86 180 bottom
R7NN  2K  [R0402]  167.13 197.69 180 bottom
R7Q  68.1K  [R0402]  187.36 198.7 270 bottom
R7X  2K  [R0402]  170.3 197.69 180 bottom
R8  0  [R0603]  185.93 180.04 0 top
R8FF  1K  [R0402]  165.48 139.95 180 top
R8LL  1.07MEG  [R0805]  172.24 218.9 180 top
R8M  10  [R0402]  188.47 183.72 0 top
R9LL  402K  [R0402]  181.64 211.28 0 top
R9Q  13.0K  [R0603]  191.04 204.67 270 bottom
R10  200  [R0402]  192.74 215.26 180 top
R10LL  14.3K  [R0805]  168.53 211.15 270 top
R10Q  20K  [R0402]  188.88 200.99 180 bottom
R11  33  [R0201]  164.59 150.32 270 top
R11AA  10K  [R0402]  162.68 155.02 0 bottom
R11FF  1K  [R0402]  163.27 139.98 0 top
R11LL  402K  [R0402]  172.37 213.44 180 top
R12  33  [R0201]  164.84 148.03 90 top
R12FF  10K  [R0402]  161.67 120.9 180 top
R12LL  23.7K  [R0402]  172.37 212.29 180 top
R13  33  [R0201]  162.05 147.78 180 top
R13FF  10K  [R0402]  163.7 120.9 0 top
R14  0  [R0402]  186.21 216.74 180 top
R14FF  10K  [R0402]  168.02 120.9 180 top
R14LL  100K  [R0402]  181.39 220.29 180 top
R15FF  10K  [R0402]  170.05 120.9 0 top
R16FF  10K  [R0402]  153.16 113.41 0 top
R16LL  255K  [R0402]  181.77 216.36 0 top
R17  0  [R1206]  186.43 186.77 270 bottom
R17FF  10K  [R0402]  153.16 112.27 0 top
R18  1  [R1206]  181.01 223.6 0 top
R18FF  10K  [R0402]  160.78 113.41 0 top
R18LL  2K  [R0402]  168.43 215.09 0 top
R19FF  10K  [R0402]  160.78 112.27 0 top
R20  45.3K  [R0201]  168.05 211.02 270 bottom
R20FF  10K  [R0402]  169.04 113.41 0 top
R21  45.3K  [R0201]  184.05 211.28 270 bottom
R21FF  10K  [R0402]  169.04 112.27 0 top
R21LL  10K  [R0402]  183.17 211.15 90 top
R22  0  [R0603]  171.45 183.72 270 bottom
R22LL  24.9K  [R0402]  168.94 218.52 180 bottom
R23  50  [R0402]  155.57 118.06 180 top
R23LL  13.7K  [R0805]  184.78 211.41 270 top
R24LL  10.5K  [R0603]  166.66 215.98 90 top
R25  56.2  [R0402]  154.1 117.35 270 bottom
R26  71.5K  [R0402]  183.17 223.34 0 bottom
R27  100K  [R0402]  183.17 224.48 0 bottom
R28  0  [R1206]  176.56 230.07 180 bottom
R29  100K  [R0402]  189.99 186.77 270 bottom
R30  100K  [R0402]  177.29 186.39 90 bottom
R31  100K  [R0402]  172.13 186.86 0 top
R33FF  10K  [R0402]  146.73 101.37 0 top
R34FF  10K  [R0402]  144.4 101.45 180 top
R44LL  60.4K  [R0402]  172.88 215.72 180 bottom
R51LL  10K  [R0402]  181.77 215.21 0 top
R700  1.5K  [R0402]  185.07 226.52 270 bottom
RESET  7914G-1-000E  [SWSMSQ197H165-2]  136.45 106.68 0 top
T1  LDB184G6BAAEA048  [TSML63W31H29]  128.14 151.33 0 top
T1D  NCR2-123+  [NF1846-1]  145.16 169.16 0 top
T1R  TCM1-83X+  [TSML150W160H160]  151.23 188.62 0 top
T1S  TCM1-83X+  [TSML150W160H160]  156.46 181.34 180 bottom
T1T  TCM1-83X+  [TSML150W160H160]  155.17 156.69 0 bottom
T1U  TCM1-83X+  [TSML150W160H160]  158.37 182.28 0 top
T1V  TCM1-83X+  [TSML150W160H160]  159.64 156.06 180 top
T1W  TCM1-83X+  [TSML150W160H160]  147.59 177.43 45 top
T1X  TCM1-83X+  [TSML150W160H160]  148.26 174.4 235 bottom
T1Y  TCM1-83X+  [TSML150W160H160]  147.8 164.95 305 bottom
T1Z  TCM1-83X+  [TSML150W160H160]  148.49 159.97 135 top
T2  LDB184G6BAAEA048  [TSML63W31H29]  128.14 148.54 0 top
T3  LDB184G6BAAEA048  [TSML63W31H29]  148.21 173.66 324 bottom
T4  LDB183G0BAADA042TEMP  [TSML63W31H29]  146.81 151.33 0 top
T5  LDB183G0BAADA042TEMP  [TSML63W31H29]  146.81 148.41 0 top
T6  LDB184G6BAAEA048  [TSML63W31H29]  148.49 164.64 35 bottom
T7  LDB183G0BAADA042TEMP  [TSML63W31H29]  159 181.9 270 top
T8  LDB183G0BAADA042TEMP  [TSML63W31H29]  155.79 157.07 90 bottom
T9  LDB184G6BAAEA048  [TSML63W31H29]  148.31 177.62 315 top
T10  LDB184G6BAAEA048  [TSML63W31H29]  148.31 160.71 45 top
T11  LDB183G0BAADA042TEMP  [TSML63W31H29]  159 156.44 90 top
T12  LDB183G0BAADA042TEMP  [TSML63W31H29]  155.83 180.95 270 bottom
TP1  TESTPAD  [TPSMC30]  161.16 158.19 180 bottom
TP1A  WHT  [CNKEY5001TP]  192.63 234.27 180 top
TP1K  TESTPAD  [TPSMC30]  169.44 105.03 180 bottom
TP2  TESTPAD  [TPSMC30]  161.8 159.59 180 bottom
TP2A  BLK  [CNKEY5001TP]  192.76 230.84 180 top
TP3K  TESTPAD  [TPSMC30]  151.38 101.85 180 bottom
TP4K  TESTPAD  [TPSMC30]  193.16 103.84 0 top
TP5K  TESTPAD  [TPSMC30]  164.03 102.62 180 bottom
TP6  TESTPAD  [TPSMC30]  146.9 214.06 0 top
TP7K  TESTPAD  [TPSMC30]  162.36 102.64 180 bottom
TP9  TESTPAD  [TPSMC30]  151.71 149.87 0 top
TP9K  TESTPAD  [TPSMC30]  151.38 103.63 180 bottom
TP10K  TESTPAD  [TPSMC30]  171.83 191.97 0 top
TP12K  TESTPAD  [TPSMC30]  144.52 103.84 180 bottom
TP13K  WHT  [CNKEY5001TP]  187.61 218.13 0 top
TP14K  TESTPAD  [TPSMC30]  154.94 130.51 0 top
TP15K  TESTPAD  [TPSMC30]  177.16 107.14 0 top
TP16K  TESTPAD  [TPSMC30]  184.15 101.93 0 top
TP17K  TESTPAD  [TPSMC30]  184.15 234.79 0 top
TP18K  TESTPAD  [TPSMC30]  184.15 164.94 0 top
U1  AD7175-8BCPZ  [QFN40_6X6_PAD3_9X3_9]  146.56 217.37 180 bottom
U1AA  AD9986BBPZ  [LFBGA324]  159.01 169.15 270 top
U1B  HMC7044LP10BE  [QFN68_10X10_PAD6_3X6_3]  147.25 112.63 90 bottom
U1FF  FXL4TD245BQX  [DQFN16_3_5X2_5_PAD2_15X1_15]  168.66 148.34 270 top
U1K  M24C02-RDW6TP  [TSSOP8]  173.86 102.62 270 bottom
U1LL  ADP5056ACCZ  [LGA43]  177.7 214.58 90 top
U1M  ADP1765ACPZ-1.0  [QFN16_3X3_PAD1_7X1_7]  186.84 186.82 180 top
U1NN  ADP1765ACPZ-1.0  [QFN16_3X3_PAD1_7X1_7]  168.45 185.04 180 top
U1P  ADM7155ACPZ-02  [QFN8_3X3_PAD2_44X1_7]  190.02 222.99 90 top
U1Q  ADP7102ACPZ  [QFN8_3X3_PAD2_44X1_7]  187.61 203.4 270 bottom
U1X  ADP1765ACPZ-1.0  [QFN16_3X3_PAD1_7X1_7]  177.47 182.81 270 top
U2FF  FXL4TD245BQX  [DQFN16_3_5X2_5_PAD2_15X1_15]  168.66 140.72 270 top
U3  ADP7112ACBZ-5.0-R7  [WLCSP6_B]  142.62 211.36 180 bottom
U3FF  FXL4TD245BQX  [DQFN16_3_5X2_5_PAD2_15X1_15]  168.66 132.46 270 top
U4FF  FXL4TD245BQX  [DQFN16_3_5X2_5_PAD2_15X1_15]  162.31 124.21 270 top
U5FF  FXL4TD245BQX  [DQFN16_3_5X2_5_PAD2_15X1_15]  168.66 124.21 270 top
U6FF  NLSX5014MUTAG  [UQFN12_2X1_7]  153.67 115.7 90 top
U7FF  NLSX5014MUTAG  [UQFN12_2X1_7]  161.29 115.7 90 top
U8FF  NLSX5014MUTAG  [UQFN12_2X1_7]  169.54 115.7 90 top
U10FF  NLSX5014MUTAG  [UQFN12_2X1_7]  146.81 103.38 90 top
U100  ADP7158ACPZ-3.3-R7  [DFN10_3X3_PAD2_38X1_64]  181.01 226.9 270 bottom
Y1B  122.88MEGHZ  [YSML276W197H63]  162.11 114.16 180 bottom
Y2B  122.88MEGHZ  [LCC4H210]  162 123.65 0 bottom

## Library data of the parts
3P3V 12P0V GND0-GND3 = CNTP1P: User Part Number: UPN; Tolerance: N/A; alternate symbols: (); part number: CNTP1P_SM-RCU-0C,E030355,CNTERCU; tolerance: N/A
ADC0-ADC3 DAC0-DAC3 EXT_CLK = CNBNC4P: alternate symbols: (); part number: CNBNC4P_SM-142-0761-841,E015238,CNSMAL554W247H118; tolerance: N/A
ADC_CLK EXT_HMCREF EXT_SYNC EXT_SYS_N EXT_SYS_P = CNBNC2P: Tolerance: N/A; User Part Number: UPN; alternate symbols: (); part number: CNBNC2P_SM-85305-0232,E023859,CNSMASQ197H161; tolerance: N/A
AGC GPIO = CN16P_ODD_EVEN: Tolerance: N/A; User Part Number: UPN; alternate symbols: (); part number: CN16P_ODD_EVEN_SM-FTSH-108-01-F-DV-K,E025352,CNHDR2X8H251; tolerance: N/A
C1 C2 = CAP: User Part Number: UPN; Tolerance: 10; alternate symbols: (C0402L); part number: CAP_SM-1UF,10V,10,E028140,C0402; tolerance: 10
C1A = CAP: Tolerance: 10; User Part Number: UPN; alternate symbols: (); part number: CAP_SM-10UF,16V,10,E018459,C1210-2; tolerance: 10
C1AA C1C C1R C1S C1T C1U C1V C2AA C2C C2R C2S C2T C2U C2V C2X C2Y C3 C3C C3D C3R C3S C3T C3U C3V C4 C4AA C4C C4D C5 C5AA C5D C6 C6AA C6D C7 C7AA C8 C8AA C9 C9AA C10AA C11AA C12AA C13AA C14AA C15AA C16AA C17 C17AA C18 C18AA C19 C19AA C20 C20AA C21AA C22AA C23AA C24AA C25AA C27AA C29AA C30AA C31AA C32AA C33AA C34AA C35AA C36AA C37AA C38AA C39AA C40AA C41AA C42AA C43AA C44AA C45AA C46AA C47AA C48AA C49AA C50AA C51AA C52AA C53AA C54AA C55AA C56AA C57AA C58AA C59AA C60AA C70AA C71AA C72AA = CAP: alternate symbols: (C0201L); part number: CAP_SM-0.1UF,25V,10,E022721,C0201; tolerance: 10
C1B C2B C5B C18B C19B = CAP: User Part Number: UPN; Tolerance: 20; alternate symbols: (C0402L); part number: CAP_SM-4.7UF,6.3V,20,E014207,C0402; tolerance: 20
C1D C2D = CAP: User Part Number: UPN; Tolerance: 0.25pF; alternate symbols: (C0402L); part number: CAP_SM-1.5PF,50V,0.25PF,E012549,C0402; tolerance: 0.25pF
C1FF C1K C2FF C3FF C4FF C5FF C6B C6FF C7B C8FF C9FF C10FF C11B C11FF C12B C12FF C13B C13FF C14FF C15B C15FF C16B C16FF C17B C17FF C18FF C19FF C20B C21B C22B C23B C24B C25B C26B C27B C28B = CAP: User Part Number: UPN; Tolerance: 10; alternate symbols: (C0402L); part number: CAP_SM-0.1UF,16V,10,E018707,C0402; tolerance: 10
C1G C1H C1I C1J C2G C2H C2I C2J C3G C3H C3I C3J C4G C4H C4I C4J C5G C5H C5I C5J C6G C6H C6I C6J C7G C7H C7I C7J C8G C8H C8I C8J C29B C30B C31B C32B C33B C34B C35B C36B C37B C38B C39B C40B = CAP: alternate symbols: (C0201L); part number: CAP_SM-0.1UF,25V,10,E022721,C0201; tolerance: 10; signal model: DEFAULT_CAPACITOR_100000pF_2_1
C1LL C3LL C25LL = CAP: User Part Number: UPN; Tolerance: 10; alternate symbols: (C0603L); part number: CAP_SM-0.1UF,16V,10,E026560,C0603; tolerance: 10
C1X C2M C2NN C2P C2Q C5P C5Q C8P = CAP: User Part Number: UPN; Tolerance: 20; alternate symbols: (C0603L,C0603L_ALT); part number: CAP_SM-10UF,6.3V,20,E030255,C0603; tolerance: 20
C2A C5LL C11LL C12LL C14LL C28LL C29LL = CAP: User Part Number: UPN; Tolerance: 20; alternate symbols: (C0603L); part number: CAP_SM-0.1UF,16V,20,E032308,C0603; tolerance: 20
C2LL C6LL C10LL = CAP: User Part Number: UPN; Tolerance: 2; alternate symbols: (C0402L); part number: CAP_SM-10PF,50V,2,E033515,C0402; tolerance: 2
C2W C2Z = CAP: alternate symbols: (C0201L); part number: CAP_SM-0.1UF,10V,10,E022722,C0201; tolerance: 10
C2XA C3B C3M C3NN C3P C4B C4M C4NN C4P C4Q C4X C5M C5NN C5OO C5X C6Q C7P C8B C8M C8X C9OO C9P C10NN C14OO C44B = CAP: User Part Number: UPN; Tolerance: 10; alternate symbols: (C0402L); part number: CAP_SM-1UF,6.3V,10,E030593,C0402; tolerance: 10
C4LL C22LL C23LL C24LL C27LL C42LL = CAP: Tolerance: 20; User Part Number: UPN; alternate symbols: (); part number: CAP_SM-100UF,6.3V,20,E031805,C1210-2; tolerance: 20
C6M C6X C8NN = CAP: User Part Number: UPN; Tolerance: 5; alternate symbols: (C0402L_ALT,C0402L); part number: CAP_SM-0.01UF,25V,5,E020410,C0402; tolerance: 5
C6NN C6P C7NN C9M C9X C10X C12N C15 C16 C23X = CAP: User Part Number: UPN; Tolerance: 20; alternate symbols: (C0402L); part number: CAP_SM-10UF,4V,20,E025098,C0402; tolerance: 20
C6OO C7OO C8OO C17OO C100 = CAP: User Part Number: UPN; Tolerance: 10; alternate symbols: (C0603L); part number: CAP_SM-10UF,10V,10,E031791,C0603; tolerance: 10
C7LL = CAP: Tolerance: 10; User Part Number: UPN; alternate symbols: (); part number: CAP_SM-4.7UF,16V,10,E027372,C1206H71-2; tolerance: 10
C7M C7X C9NN = CAP: Tolerance: 20; User Part Number: UPN; alternate symbols: (); part number: CAP_SM-47UF,6.3V,20,E033142,C1206H71; tolerance: 20
C8LL = CAP: User Part Number: UPN; Tolerance: 10; alternate symbols: (C0603L,C0603L_ALT); part number: CAP_SM-4.7UF,6.3V,10,E030256,C0603; tolerance: 10
C9B C10B = CAP: User Part Number: UPN; Tolerance: 5; alternate symbols: (C0402L); part number: CAP_SM-100PF,50V,5,E022402,C0402; tolerance: 5
C9LL C43LL = CAP: User Part Number: UPN; Tolerance: 10; alternate symbols: (C0402L); part number: CAP_SM-1000PF,100V,10,E034889,C0402; tolerance: 10
C10 C11 = CAP: alternate symbols: (C0201L); part number: CAP_SM-0.01UF,10V,10,E007201,C0201; tolerance: 10
C12 C13 = CAP: User Part Number: UPN; Tolerance: 10; alternate symbols: (C0603L); part number: CAP_SM-2.2UF,10V,10,E015288,C0603; tolerance: 10
C13LL = CAP: User Part Number: UPN; Tolerance: 10; alternate symbols: (C0402L); part number: CAP_SM-0.01UF,50V,10,E019413,C0402; tolerance: 10
C14 = CAP: User Part Number: UPN; Tolerance: 5; alternate symbols: (C0402L_ALT,C0402L); part number: CAP_SM-1000PF,50V,5,E012419,C0402; tolerance: 5
C30LL C31LL C41LL = CAP: Tolerance: 20; User Part Number: UPN; alternate symbols: (); part number: CAP_SM-22UF,16V,20,E034214,C1210H106; tolerance: 20
C40LL = CAP: User Part Number: UPN; Tolerance: 10; alternate symbols: (C0402L); part number: CAP_SM-2200PF,100V,10,E021542,C0402; tolerance: 10
C41B = CAP: Tolerance: 5; User Part Number: UPN; alternate symbols: (); part number: CAP_SM-160PF,50V,5,E025262,C0402H22; tolerance: 5
C42B C43B = CAP: User Part Number: UPN; Tolerance: 5; alternate symbols: (C0402L); part number: CAP_SM-4700PF,10V,5,E021174,C0402; tolerance: 5
C62AA = CAP: alternate symbols: (C0201L); part number: CAP_SM-0.022UF,16V,10,E022120,C0201; tolerance: 10
C63AA = CAP: alternate symbols: (C0201L); part number: CAP_SM-0.033UF,6.3V,10,E017459,C0201; tolerance: 10
C65AA = CAP: alternate symbols: (C0201L); part number: CAP_SM-2200PF,10V,10,E021478,C0201; tolerance: 10
C69AA = CAP: Tolerance: 20; User Part Number: UPN; alternate symbols: (); part number: CAP_SM-2.2UF,10V,20,E026436,C0402H22; tolerance: 20
D1A = DIO: Tolerance: N/A; User Part Number: UPN; alternate symbols: (); part number: DIO_SM-SMAJ12A,N/A,N/A,E001101,DIOSMJ5_0; tolerance: N/A
DS1M DS1NN DS1P DS1Q DS1X DS100 = DIOLED: User Part Number: UPN; Tolerance: N/A; alternate symbols: (); part number: DIOLED_SM-APHHS1005LSYCK/J3-PF,1.85V,N/A,E032958,LED0402_A; tolerance: N/A
E1 E1M E1NN E1OO E1XX E2 E2NN E2OO E2XX E3OO E4NN E4X = FERRITE: Tolerance: N/A; User Part Number: UPN; alternate symbols: (); part number: FERRITE_SM-22OHM AT 100 MEGHZ,N/A,E032882,L0603H28; tolerance: N/A
E1B E2B = FERRITE: User Part Number: UPN; Tolerance: 25; alternate symbols: (L0402L); part number: FERRITE_SM-120OHM,25,E010287,L0402; tolerance: 25
F1A = FSFUSE: Tolerance: N/A; User Part Number: UPN; alternate symbols: (); part number: FSFUSE_SM-3A,32V,E005229,F1206; tolerance: N/A
HMC_STATUS = DIOLED: User Part Number: UPN; Tolerance: N/A; alternate symbols: (); part number: DIOLED_SM-APHHS1005SURCK,N/A,N/A,E021838,LED0402_A; tolerance: N/A
JP1 = NC3P_JMPR: Tolerance: N/A; User Part Number: UPN; alternate symbols: (); part number: NC3P_JMPR_SM-3PINJUMPER_0603,E031098,JUMPER0603_3P; tolerance: N/A
L1D L2D = IND: Tolerance: 5; User Part Number: UPN; alternate symbols: (L0201L); part number: IND_SM-3.6NH,5,E022818,L0201; tolerance: 5
L1LL L2LL = IND: Tolerance: 20; User Part Number: UPN; alternate symbols: (); part number: IND_SM-800NH,20,E022526,LSML208W216H122_A; tolerance: 20
L3LL = IND: User Part Number: UPN; Tolerance: 20; alternate symbols: (); part number: IND_SM-4.7UH,20,E013623,LSMSQ157H122; tolerance: 20
P1 = CN2P: User Part Number: UPN; Tolerance: N/A; alternate symbols: (); part number: CN2P_TH-B2B-XH-A(LF)(SN),E021915,CNHDR1X2H276; tolerance: N/A
P1AA = CN3P: Tolerance: N/A; User Part Number: UPN; alternate symbols: (); part number: CN3P_TH-PJ-102AH,E010074,CNCUI-PJ-102A; tolerance: N/A
P1K = CN400P_A_K_V2: User Part Number: UPN; Tolerance: N/A; alternate symbols: (); part number: CN400P_A_K_V2_SM-ASP-134488-01,E011384,CNSAMTECASP-134488-01; tolerance: N/A
Q1M Q1NN Q1Q Q1X = TRANBSS138: User Part Number: UPN; Tolerance: N/A; alternate symbols: (); part number: TRANBSS138_SM-NDS331N,E012840,SOT23; tolerance: N/A
R1 R1M R1XA = RES: User Part Number: UPN; Tolerance: 0.5; alternate symbols: (); part number: RES_SM-0.05,E039387,3W,0.5,R2512H35; tolerance: 0.5
R1A = RES: User Part Number: UPN; Tolerance: 5; alternate symbols: (R0603L); part number: RES_SM-10,E020147,1/10W,5,R0603; tolerance: 5
R1B R25 = RES: User Part Number: UPN; Tolerance: 1; alternate symbols: (R0402L); part number: RES_SM-56.2,E012977,1/10W,1,R0402; tolerance: 1
R1C = RES: User Part Number: UPN; Tolerance: 1; alternate symbols: (R0402L); part number: RES_SM-100,E016329,1/10W,1,R0402; tolerance: 1
R1E R2E R2LL R14 = RES: User Part Number: UPN; Tolerance: JUMPER; alternate symbols: (R0402L,R0402L_ALT); part number: RES_SM-0,E003438,1/10W,JUMPER,R0402; tolerance: JUMPER
R1FF R1K R2FF R3B R3FF R4 R4B R4FF R5 R5FF R6FF R7FF R11AA R12FF R13FF R14FF R15FF R16FF R17FF R18FF R19FF R20FF R21FF R33FF R34FF = RES: User Part Number: UPN; Tolerance: 1; alternate symbols: (R0402L,R0402L_ALT); part number: RES_SM-10K,E003751,1/10W,1,R0402; tolerance: 1
R1LL R4LL R4M R4NN R4X R5P R21LL R51LL = RES: User Part Number: UPN; Tolerance: 0.1; alternate symbols: (R0402L); part number: RES_SM-10K,E012474,1/16W,0.1,R0402; tolerance: 0.1
R1Q R7M R7NN R7X R18LL = RES: User Part Number: UPN; Tolerance: 0.1; alternate symbols: (R0402L); part number: RES_SM-2K,E031286,1/16W,0.1,R0402; tolerance: 0.1
R1W R1X R1Y R1Z = RES: alternate symbols: (R0201NC,R0201L); part number: RES_SM-100,E007239,1/20W,1,R0201; tolerance: 1
R2 = RES: Tolerance: JUMPER; User Part Number: UPN; alternate symbols: (R1210L); part number: RES_SM-0,E018060,3/4W,JUMPER,R1210; tolerance: JUMPER
R2AA = RES: alternate symbols: (R0201L); part number: RES_SM-4.99K,E027454,1/20W,1,R0201; tolerance: 1
R2B R7LL R8FF R11FF = RES: User Part Number: UPN; Tolerance: 1; alternate symbols: (R0402L,R0402L_ALT); part number: RES_SM-1K,E003763,1/10W,1,R0402; tolerance: 1
R2K = RES: alternate symbols: (R0201L); part number: RES_SM-0,E004015,1/20W,JUMPER,R0201; tolerance: JUMPER
R2M R2P R3M R6Q R27 = RES: User Part Number: UPN; Tolerance: 1; alternate symbols: (R0402L); part number: RES_SM-100K,E017855,1/16W,1,R0402; tolerance: 1
R3 R6 R7 R11-R13 = RES: alternate symbols: (R0201L); part number: RES_SM-33,E011241,1/20W,1,R0201; tolerance: 1
R3AA = RES: User Part Number: UPN; Tolerance: 1; alternate symbols: (R0402L); part number: RES_SM-226,E015429,1/10W,1,R0402; tolerance: 1
R3P R26 = RES: User Part Number: UPN; Tolerance: 1; alternate symbols: (R0402L); part number: RES_SM-71.5K,E019735,1/16W,1,R0402; tolerance: 1
R4Q = RES: User Part Number: UPN; Tolerance: 1; alternate symbols: (R0603L); part number: RES_SM-100K,E010279,1/10W,1,R0603; tolerance: 1
R5B = RES: User Part Number: UPN; Tolerance: 1; alternate symbols: (R0402L); part number: RES_SM-430,E015617,1/10W,1,R0402; tolerance: 1
R5X R8M = RES: User Part Number: UPN; Tolerance: 1; alternate symbols: (R0402L,R0402L_ALT); part number: RES_SM-10,E003768,1/10W,1,R0402; tolerance: 1
R6B = RES: User Part Number: UPN; Tolerance: 1; alternate symbols: (R0402L); part number: RES_SM-11K,E015614,1/10W,1,R0402; tolerance: 1
R6M R6NN R6X R29-R31 = RES: User Part Number: UPN; Tolerance: 5; alternate symbols: (R0402L); part number: RES_SM-100K,E003464,1/10W,5,R0402; tolerance: 5
R6P = RES: User Part Number: UPN; Tolerance: 0.1; alternate symbols: (R0402L); part number: RES_SM-15K,E014275,1/16W,0.1,R0402; tolerance: 0.1
R7Q = RES: User Part Number: UPN; Tolerance: 1; alternate symbols: (R0402L); part number: RES_SM-68.1K,E014436,1/10W,1,R0402; tolerance: 1
R8 = RES: User Part Number: UPN; Tolerance: JUMPER; alternate symbols: (R0603L); part number: RES_SM-0,E006826,1/10W,JUMPER,R0603; tolerance: JUMPER
R8LL = RES: User Part Number: UPN; Tolerance: 1; alternate symbols: (R0805L); part number: RES_SM-1.07MEG,E032844,1/8W,1,R0805; tolerance: 1
R9LL R11LL = RES: User Part Number: UPN; Tolerance: 1; alternate symbols: (R0402L); part number: RES_SM-402K,E020472,1/10W,1,R0402; tolerance: 1
R9Q = RES: User Part Number: UPN; Tolerance: 1; alternate symbols: (R0603L); part number: RES_SM-13.0K,E003742,1/10W,1,R0603; tolerance: 1
R10 = RES: User Part Number: UPN; Tolerance: 0.5; alternate symbols: (R0402L); part number: RES_SM-200,E022007,1/16W,0.5,R0402; tolerance: 0.5
R10LL = RES: User Part Number: UPN; Tolerance: 1; alternate symbols: (R0805L); part number: RES_SM-14.3K,E012818,1/8W,1,R0805; tolerance: 1
R10Q = RES: User Part Number: UPN; Tolerance: 1; alternate symbols: (R0402L,R0402L_ALT); part number: RES_SM-20K,E003791,1/10W,1,R0402; tolerance: 1
R12LL = RES: User Part Number: UPN; Tolerance: 1; alternate symbols: (R0402L); part number: RES_SM-23.7K,E016740,1/10W,1,R0402; tolerance: 1
R14LL = RES: User Part Number: UPN; Tolerance: 1; alternate symbols: (R0402L,R0402L_ALT); part number: RES_SM-100K,E003796,1/10W,1,R0402; tolerance: 1
R16LL = RES: User Part Number: UPN; Tolerance: 1; alternate symbols: (R0402L); part number: RES_SM-255K,E032891,1/10W,1,R0402; tolerance: 1
R17 R28 = RES: User Part Number: UPN; Tolerance: JUMPER; alternate symbols: (R1206L); part number: RES_SM-0,E004448,1/4W,JUMPER,R1206; tolerance: JUMPER
R18 = RES: User Part Number: UPN; alternate symbols: (R1206L); part number: RES_SM-1,E003121,1/8W,1,R1206
R20 R21 = RES: alternate symbols: (R0201L); part number: RES_SM-45.3K,E034793,1/20W,1,R0201; tolerance: 1
R22 = RES: User Part Number: UPN; Tolerance: N/A; alternate symbols: (R0603L); part number: RES_SM-0,E005803,N/A,N/A,R0603; tolerance: N/A
R22LL = RES: User Part Number: UPN; Tolerance: 1; alternate symbols: (R0402L); part number: RES_SM-24.9K,E007443,1/10W,1,R0402; tolerance: 1
R23 = RES: User Part Number: UPN; Tolerance: 1; alternate symbols: (R0402L); part number: RES_SM-50,E012326,1/20W,1,R0402; tolerance: 1
R23LL = RES: User Part Number: UPN; Tolerance: 1; alternate symbols: (R0805L); part number: RES_SM-13.7K,E003644,1/8W,1,R0805; tolerance: 1
R24LL = RES: User Part Number: UPN; Tolerance: 0.1; alternate symbols: (R0603L); part number: RES_SM-10.5K,E018488,1/10W,0.1,R0603; tolerance: 0.1
R44LL = RES: User Part Number: UPN; Tolerance: 1; alternate symbols: (R0402L); part number: RES_SM-60.4K,E022436,1/10W,1,R0402; tolerance: 1
R700 = RES: User Part Number: UPN; Tolerance: 1; alternate symbols: (R0402L); part number: RES_SM-1.5K,E003782,1/10W,1,R0402; tolerance: 1
RESET = SWSPST4PIN_V2: User Part Number: UPN; Tolerance: N/A; alternate symbols: (); part number: SWSPST4PIN_V2_SM-7914G-1-000E,E014175,SWSMSQ197H165-2; tolerance: N/A
T1-T3 T6 T9 T10 = XFMR6P_V5: User Part Number: UPN; Tolerance: N/A; alternate symbols: (); part number: XFMR6P_V5_SM-LDB184G6BAAEA048,E041249,TSML63W31H29; tolerance: N/A
T1D = XFMRRF_6P_V4: Tolerance: N/A; User Part Number: UPN; alternate symbols: (); part number: XFMRRF_6P_V4_SM-NCR2-123+,E022774,NF1846-1; tolerance: N/A
T1R T1S T1T T1U T1V T1W T1X T1Y T1Z = XFMRTCMXXXX_V5: Tolerance: N/A; User Part Number: UPN; alternate symbols: (); part number: XFMRTCMXXXX_V5_SM-TCM1-83X+,E018600,TSML150W160H160; tolerance: N/A
T4 T5 T7 T8 T11 T12 = XFMR6P_V5: User Part Number: UPN; Tolerance: N/A; alternate symbols: (); part number: XFMR6P_V5_SM-LDB183G0BAADA042TEMP,E041248,TSML63W31H29; tolerance: N/A
TP1 TP1K TP2 TP3K TP4K TP5K TP6 TP7K TP9 TP9K TP10K TP12K TP14K TP15K TP16K TP17K TP18K = NCTESTPAD: Tolerance: N/A; User Part Number: UPN; alternate symbols: (); part number: NCTESTPAD_SM-TESTPAD,E012884,TPSMC30; tolerance: N/A
TP1A TP13K = CNTP1P: Tolerance: N/A; User Part Number: UPN; alternate symbols: (); part number: CNTP1P_TH-WHT,E005683,CNKEY5001TP; tolerance: N/A
TP2A = CNTP1P: Tolerance: N/A; User Part Number: UPN; alternate symbols: (); part number: CNTP1P_TH-BLK,E022951,CNKEY5001TP; tolerance: N/A
U1 = AD7175_8: alternate symbols: (); part number: AD7175_8_SM-AD7175-8BCPZ,E023815,QFN40_6X6_PAD3_9X3_9; tolerance: N/A
U1AA = AD9986_V2: User Part Number: UPN; Tolerance: N/A; alternate symbols: (); part number: AD9986_V2_SM-AD9986BBPZ,E038180,LFBGA324; tolerance: N/A
U1B = ADHMC7044: User Part Number: UPN; Tolerance: N/A; alternate symbols: (); part number: ADHMC7044_SM-HMC7044LP10BE,E021514,QFN68_10X10_PAD6_3X6_3; tolerance: N/A
U1FF U2FF U3FF U4FF U5FF = ICFXL4TD245: Tolerance: N/A; User Part Number: UPN; alternate symbols: (); part number: ICFXL4TD245_SM-FXL4TD245BQX,E014936,DQFN16_3_5X2_5_PAD2_15X1_15; tolerance: N/A
U1K = ICM24CXX: Tolerance: N/A; User Part Number: UPN; alternate symbols: (); part number: ICM24CXX_SM-M24C02-RDW6TP,E027045,TSSOP8; tolerance: N/A
U1LL = ADP5056: Tolerance: N/A; User Part Number: UPN; alternate symbols: (); part number: ADP5056_SM-ADP5056ACCZ,E032706,LGA43; tolerance: N/A
U1M U1NN U1X = ADP1765: Tolerance: N/A; User Part Number: UPN; alternate symbols: (); part number: ADP1765_SM-ADP1765ACPZ-1.0,E023751,QFN16_3X3_PAD1_7X1_7; tolerance: N/A
U1P = ADM7155: Tolerance: N/A; User Part Number: UPN; alternate symbols: (); part number: ADM7155_SM-ADM7155ACPZ-02,E023769,QFN8_3X3_PAD2_44X1_7; tolerance: N/A
U1Q = ADP7102: Tolerance: N/A; User Part Number: UPN; alternate symbols: (); part number: ADP7102_SM-ADP7102ACPZ,E014580,QFN8_3X3_PAD2_44X1_7; tolerance: N/A
U3 = ADP7112: alternate symbols: (); part number: ADP7112_SM-ADP7112ACBZ-5.0-R7,E025018,WLCSP6_B; tolerance: N/A
U6FF U7FF U8FF U10FF = ICNLSX5014: User Part Number: UPN; Tolerance: N/A; alternate symbols: (); part number: ICNLSX5014_SM-NLSX5014MUTAG,E023410,UQFN12_2X1_7; tolerance: N/A
U100 = ADP7158: Tolerance: N/A; User Part Number: UPN; alternate symbols: (); part number: ADP7158_SM-ADP7158ACPZ-3.3-R7,E026011,DFN10_3X3_PAD2_38X1_64; tolerance: N/A
Y1B = XTALOSC6P_V10: User Part Number: UPN; Tolerance: 5; alternate symbols: (); part number: XTALOSC6P_V10_SM-122.88MEGHZ,E019195,YSML276W197H63; tolerance: 5
Y2B = XTALCPP: Tolerance: N/A; User Part Number: UPN; alternate symbols: (); part number: XTALCPP_SM-122.88MEGHZ,E032590,LCC4H210; tolerance: N/A

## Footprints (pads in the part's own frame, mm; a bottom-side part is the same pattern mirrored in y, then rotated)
C0201
  rect 0.305x0.406 smd: 1(-0.318,0) 2(0.318,0)
C0402
  rect 0.584x0.66 smd: 1(-0.5,0) 2(0.5,0)
C0402H22
  rect 0.559x0.508 smd: 1(-0.479,0) 2(0.479,0)
C0603
  rect 0.94x0.991 smd: 1(-0.8,0) 2(0.8,0)
C1206H71
  rect 1.6x2.007 smd: 1(-1.397,0) 2(1.397,0)
C1206H71-2
  rect 1.346x1.194 smd: 1(-1.423,0) 2(1.423,0)
C1210-2
  rect 1.575x2.692 smd: 1(-1.397,0) 2(1.397,0)
C1210H106
  rect 1.092x2.057 smd: 1(-1.646,0) 2(1.646,0)
CNCUI-PJ-102A
  round 2.413 hole 1.905: 1(0,0) 2(6,0) 3(3,4.7)
CNHDR1X2H276
  rect 1.778x1.778 hole 1.27: 1(0,0)
  round 1.778 hole 1.27: 2(2.5,0)
CNHDR2X8H251
  rect 0.737x2.794 smd: 1(-4.445,-2.032) 2(-4.445,2.032) 3(-3.175,-2.032) 4(-3.175,2.032) 5(-1.905,-2.032) 6(-1.905,2.032) 7(-0.635,-2.032) 8(-0.635,2.032) 9(0.635,-2.032) 10(0.635,2.032) 11(1.905,-2.032) 12(1.905,2.032) 13(3.175,-2.032) 14(3.175,2.032) 15(4.445,-2.032) 16(4.445,2.032)
CNKEY5001TP
  round 1.524 hole 1.016: 1(0,0)
CNSAMTECASP-134488-01
  round 2.54 hole 1.27 unplated: (-27.191,0) (27.191,3.048)
  round 0.635 smd: A1(-24.765,-5.715) A2(-23.495,-5.715) A3(-22.225,-5.715) A4(-20.955,-5.715) A5(-19.685,-5.715) A6(-18.415,-5.715) A7(-17.145,-5.715) A8(-15.875,-5.715) A9(-14.605,-5.715) A10(-13.335,-5.715) A11(-12.065,-5.715) A12(-10.795,-5.715) A13(-9.525,-5.715) A14(-8.255,-5.715) A15(-6.985,-5.715) A16(-5.715,-5.715) A17(-4.445,-5.715) A18(-3.175,-5.715) A19(-1.905,-5.715) A20(-0.635,-5.715) A21(0.635,-5.715) A22(1.905,-5.715) A23(3.175,-5.715) A24(4.445,-5.715) A25(5.715,-5.715) A26(6.985,-5.715) A27(8.255,-5.715) A28(9.525,-5.715) A29(10.795,-5.715) A30(12.065,-5.715) A31(13.335,-5.715) A32(14.605,-5.715) A33(15.875,-5.715) A34(17.145,-5.715) A35(18.415,-5.715) A36(19.685,-5.715) A37(20.955,-5.715) A38(22.225,-5.715) A39(23.495,-5.715) A40(24.765,-5.715) B1(-24.765,-4.445) B2(-23.495,-4.445) B3(-22.225,-4.445) B4(-20.955,-4.445) B5(-19.685,-4.445) B6(-18.415,-4.445) B7(-17.145,-4.445) B8(-15.875,-4.445) B9(-14.605,-4.445) B10(-13.335,-4.445) B11(-12.065,-4.445) B12(-10.795,-4.445) B13(-9.525,-4.445) B14(-8.255,-4.445) B15(-6.985,-4.445) B16(-5.715,-4.445) B17(-4.445,-4.445) B18(-3.175,-4.445) B19(-1.905,-4.445) B20(-0.635,-4.445) B21(0.635,-4.445) B22(1.905,-4.445) B23(3.175,-4.445) B24(4.445,-4.445) B25(5.715,-4.445) B26(6.985,-4.445) B27(8.255,-4.445) B28(9.525,-4.445) B29(10.795,-4.445) B30(12.065,-4.445) B31(13.335,-4.445) B32(14.605,-4.445) B33(15.875,-4.445) B34(17.145,-4.445) B35(18.415,-4.445) B36(19.685,-4.445) B37(20.955,-4.445) B38(22.225,-4.445) B39(23.495,-4.445) B40(24.765,-4.445) C1(-24.765,-3.175) C2(-23.495,-3.175) C3(-22.225,-3.175) C4(-20.955,-3.175) C5(-19.685,-3.175) C6(-18.415,-3.175) C7(-17.145,-3.175) C8(-15.875,-3.175) C9(-14.605,-3.175) C10(-13.335,-3.175) C11(-12.065,-3.175) C12(-10.795,-3.175) C13(-9.525,-3.175) C14(-8.255,-3.175) C15(-6.985,-3.175) C16(-5.715,-3.175) C17(-4.445,-3.175) C18(-3.175,-3.175) C19(-1.905,-3.175) C20(-0.635,-3.175) C21(0.635,-3.175) C22(1.905,-3.175) C23(3.175,-3.175) C24(4.445,-3.175) C25(5.715,-3.175) C26(6.985,-3.175) C27(8.255,-3.175) C28(9.525,-3.175) C29(10.795,-3.175) C30(12.065,-3.175) C31(13.335,-3.175) C32(14.605,-3.175) C33(15.875,-3.175) C34(17.145,-3.175) C35(18.415,-3.175) C36(19.685,-3.175) C37(20.955,-3.175) C38(22.225,-3.175) C39(23.495,-3.175) C40(24.765,-3.175) D1(-24.765,-1.905) D2(-23.495,-1.905) D3(-22.225,-1.905) D4(-20.955,-1.905) D5(-19.685,-1.905) D6(-18.415,-1.905) D7(-17.145,-1.905) D8(-15.875,-1.905) D9(-14.605,-1.905) D10(-13.335,-1.905) D11(-12.065,-1.905) D12(-10.795,-1.905) D13(-9.525,-1.905) D14(-8.255,-1.905) D15(-6.985,-1.905) D16(-5.715,-1.905) D17(-4.445,-1.905) D18(-3.175,-1.905) D19(-1.905,-1.905) D20(-0.635,-1.905) D21(0.635,-1.905) D22(1.905,-1.905) D23(3.175,-1.905) D24(4.445,-1.905) D25(5.715,-1.905) D26(6.985,-1.905) D27(8.255,-1.905) D28(9.525,-1.905) D29(10.795,-1.905) D30(12.065,-1.905) D31(13.335,-1.905) D32(14.605,-1.905) D33(15.875,-1.905) D34(17.145,-1.905) D35(18.415,-1.905) D36(19.685,-1.905) D37(20.955,-1.905) D38(22.225,-1.905) D39(23.495,-1.905) D40(24.765,-1.905) E1(-24.765,-0.635) E2(-23.495,-0.635) E3(-22.225,-0.635) E4(-20.955,-0.635) E5(-19.685,-0.635) E6(-18.415,-0.635) E7(-17.145,-0.635) E8(-15.875,-0.635) E9(-14.605,-0.635) E10(-13.335,-0.635) E11(-12.065,-0.635) E12(-10.795,-0.635) E13(-9.525,-0.635) E14(-8.255,-0.635) E15(-6.985,-0.635) E16(-5.715,-0.635) E17(-4.445,-0.635) E18(-3.175,-0.635) E19(-1.905,-0.635) E20(-0.635,-0.635) E21(0.635,-0.635) E22(1.905,-0.635) E23(3.175,-0.635) E24(4.445,-0.635) E25(5.715,-0.635) E26(6.985,-0.635) E27(8.255,-0.635) E28(9.525,-0.635) E29(10.795,-0.635) E30(12.065,-0.635) E31(13.335,-0.635) E32(14.605,-0.635) E33(15.875,-0.635) E34(17.145,-0.635) E35(18.415,-0.635) E36(19.685,-0.635) E37(20.955,-0.635) E38(22.225,-0.635) E39(23.495,-0.635) E40(24.765,-0.635) F1(-24.765,0.635) F2(-23.495,0.635) F3(-22.225,0.635) F4(-20.955,0.635) F5(-19.685,0.635) F6(-18.415,0.635) F7(-17.145,0.635) F8(-15.875,0.635) F9(-14.605,0.635) F10(-13.335,0.635) F11(-12.065,0.635) F12(-10.795,0.635) F13(-9.525,0.635) F14(-8.255,0.635) F15(-6.985,0.635) F16(-5.715,0.635) F17(-4.445,0.635) F18(-3.175,0.635) F19(-1.905,0.635) F20(-0.635,0.635) F21(0.635,0.635) F22(1.905,0.635) F23(3.175,0.635) F24(4.445,0.635) F25(5.715,0.635) F26(6.985,0.635) F27(8.255,0.635) F28(9.525,0.635) F29(10.795,0.635) F30(12.065,0.635) F31(13.335,0.635) F32(14.605,0.635) F33(15.875,0.635) F34(17.145,0.635) F35(18.415,0.635) F36(19.685,0.635) F37(20.955,0.635) F38(22.225,0.635) F39(23.495,0.635) F40(24.765,0.635) G1(-24.765,1.905) G2(-23.495,1.905) G3(-22.225,1.905) G4(-20.955,1.905) G5(-19.685,1.905) G6(-18.415,1.905) G7(-17.145,1.905) G8(-15.875,1.905) G9(-14.605,1.905) G10(-13.335,1.905) G11(-12.065,1.905) G12(-10.795,1.905) G13(-9.525,1.905) G14(-8.255,1.905) G15(-6.985,1.905) G16(-5.715,1.905) G17(-4.445,1.905) G18(-3.175,1.905) G19(-1.905,1.905) G20(-0.635,1.905) G21(0.635,1.905) G22(1.905,1.905) G23(3.175,1.905) G24(4.445,1.905) G25(5.715,1.905) G26(6.985,1.905) G27(8.255,1.905) G28(9.525,1.905) G29(10.795,1.905) G30(12.065,1.905) G31(13.335,1.905) G32(14.605,1.905) G33(15.875,1.905) G34(17.145,1.905) G35(18.415,1.905) G36(19.685,1.905) G37(20.955,1.905) G38(22.225,1.905) G39(23.495,1.905) G40(24.765,1.905) H1(-24.765,3.175) H2(-23.495,3.175) H3(-22.225,3.175) H4(-20.955,3.175) H5(-19.685,3.175) H6(-18.415,3.175) H7(-17.145,3.175) H8(-15.875,3.175) H9(-14.605,3.175) H10(-13.335,3.175) H11(-12.065,3.175) H12(-10.795,3.175) H13(-9.525,3.175) H14(-8.255,3.175) H15(-6.985,3.175) H16(-5.715,3.175) H17(-4.445,3.175) H18(-3.175,3.175) H19(-1.905,3.175) H20(-0.635,3.175) H21(0.635,3.175) H22(1.905,3.175) H23(3.175,3.175) H24(4.445,3.175) H25(5.715,3.175) H26(6.985,3.175) H27(8.255,3.175) H28(9.525,3.175) H29(10.795,3.175) H30(12.065,3.175) H31(13.335,3.175) H32(14.605,3.175) H33(15.875,3.175) H34(17.145,3.175) H35(18.415,3.175) H36(19.685,3.175) H37(20.955,3.175) H38(22.225,3.175) H39(23.495,3.175) H40(24.765,3.175) J1(-24.765,4.445) J2(-23.495,4.445) J3(-22.225,4.445) J4(-20.955,4.445) J5(-19.685,4.445) J6(-18.415,4.445) J7(-17.145,4.445) J8(-15.875,4.445) J9(-14.605,4.445) J10(-13.335,4.445) J11(-12.065,4.445) J12(-10.795,4.445) J13(-9.525,4.445) J14(-8.255,4.445) J15(-6.985,4.445) J16(-5.715,4.445) J17(-4.445,4.445) J18(-3.175,4.445) J19(-1.905,4.445) J20(-0.635,4.445) J21(0.635,4.445) J22(1.905,4.445) J23(3.175,4.445) J24(4.445,4.445) J25(5.715,4.445) J26(6.985,4.445) J27(8.255,4.445) J28(9.525,4.445) J29(10.795,4.445) J30(12.065,4.445) J31(13.335,4.445) J32(14.605,4.445) J33(15.875,4.445) J34(17.145,4.445) J35(18.415,4.445) J36(19.685,4.445) J37(20.955,4.445) J38(22.225,4.445) J39(23.495,4.445) J40(24.765,4.445) K1(-24.765,5.715) K2(-23.495,5.715) K3(-22.225,5.715) K4(-20.955,5.715) K5(-19.685,5.715) K6(-18.415,5.715) K7(-17.145,5.715) K8(-15.875,5.715) K9(-14.605,5.715) K10(-13.335,5.715) K11(-12.065,5.715) K12(-10.795,5.715) K13(-9.525,5.715) K14(-8.255,5.715) K15(-6.985,5.715) K16(-5.715,5.715) K17(-4.445,5.715) K18(-3.175,5.715) K19(-1.905,5.715) K20(-0.635,5.715) K21(0.635,5.715) K22(1.905,5.715) K23(3.175,5.715) K24(4.445,5.715) K25(5.715,5.715) K26(6.985,5.715) K27(8.255,5.715) K28(9.525,5.715) K29(10.795,5.715) K30(12.065,5.715) K31(13.335,5.715) K32(14.605,5.715) K33(15.875,5.715) K34(17.145,5.715) K35(18.415,5.715) K36(19.685,5.715) K37(20.955,5.715) K38(22.225,5.715) K39(23.495,5.715) K40(24.765,5.715)
